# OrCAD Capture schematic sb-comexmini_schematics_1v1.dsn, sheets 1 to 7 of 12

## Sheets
1 INDEX: title: INDEX; rev: 1.0; note: 8001006002
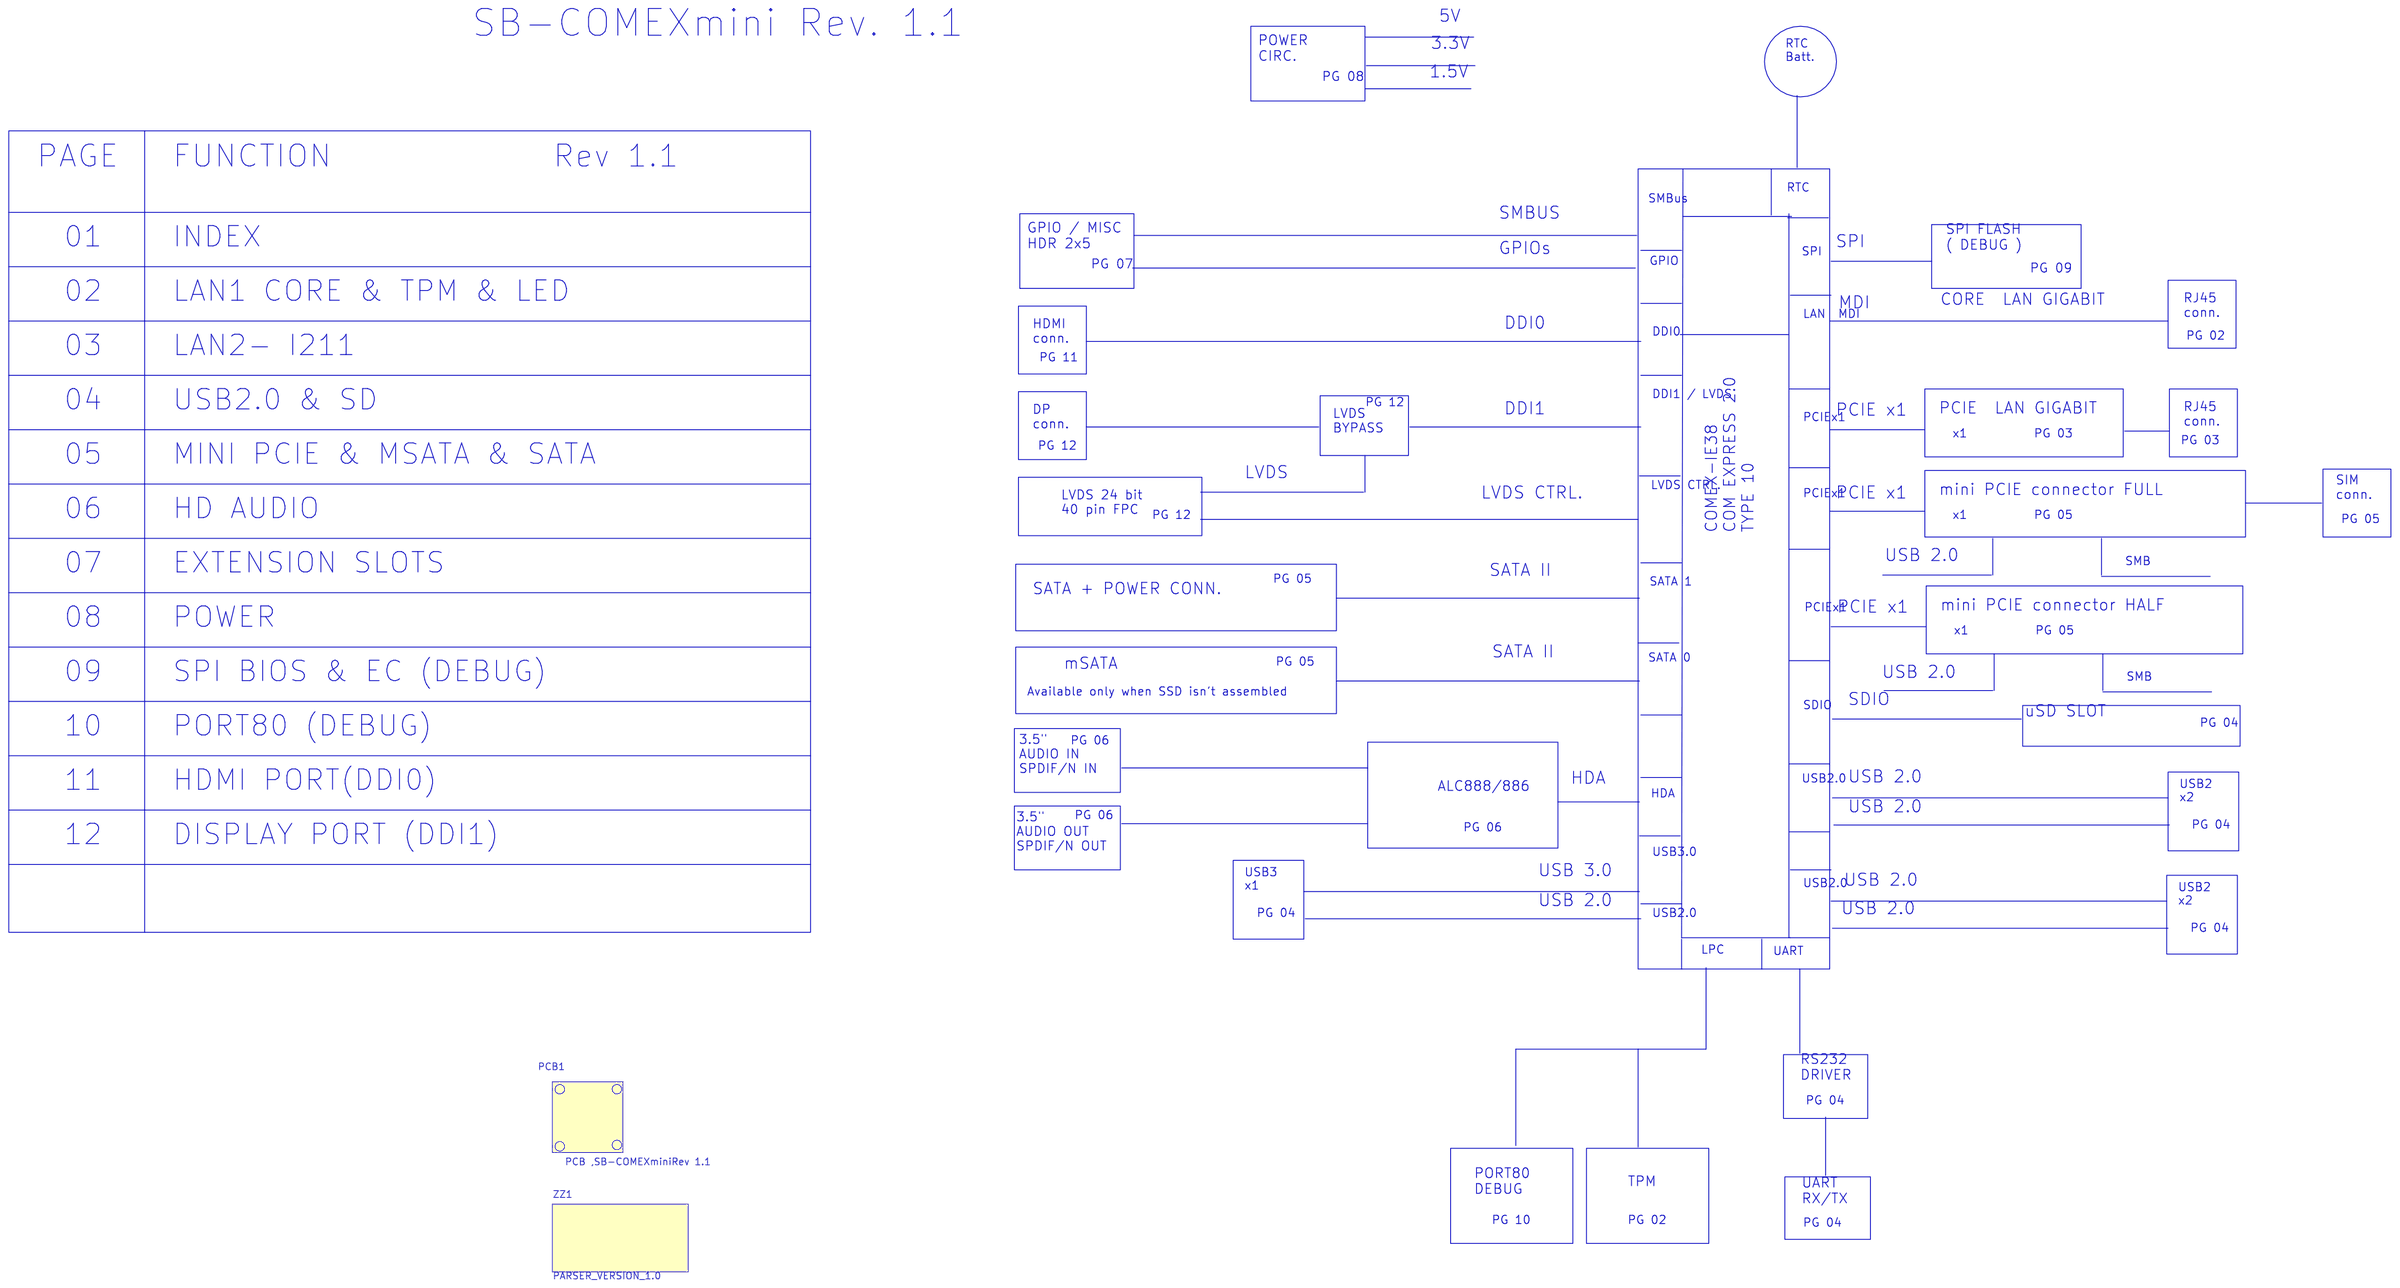
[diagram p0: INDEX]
2 LAN1 CORE & TPM & LED: size Custom; title: LAN1 CORE /TMP /LED
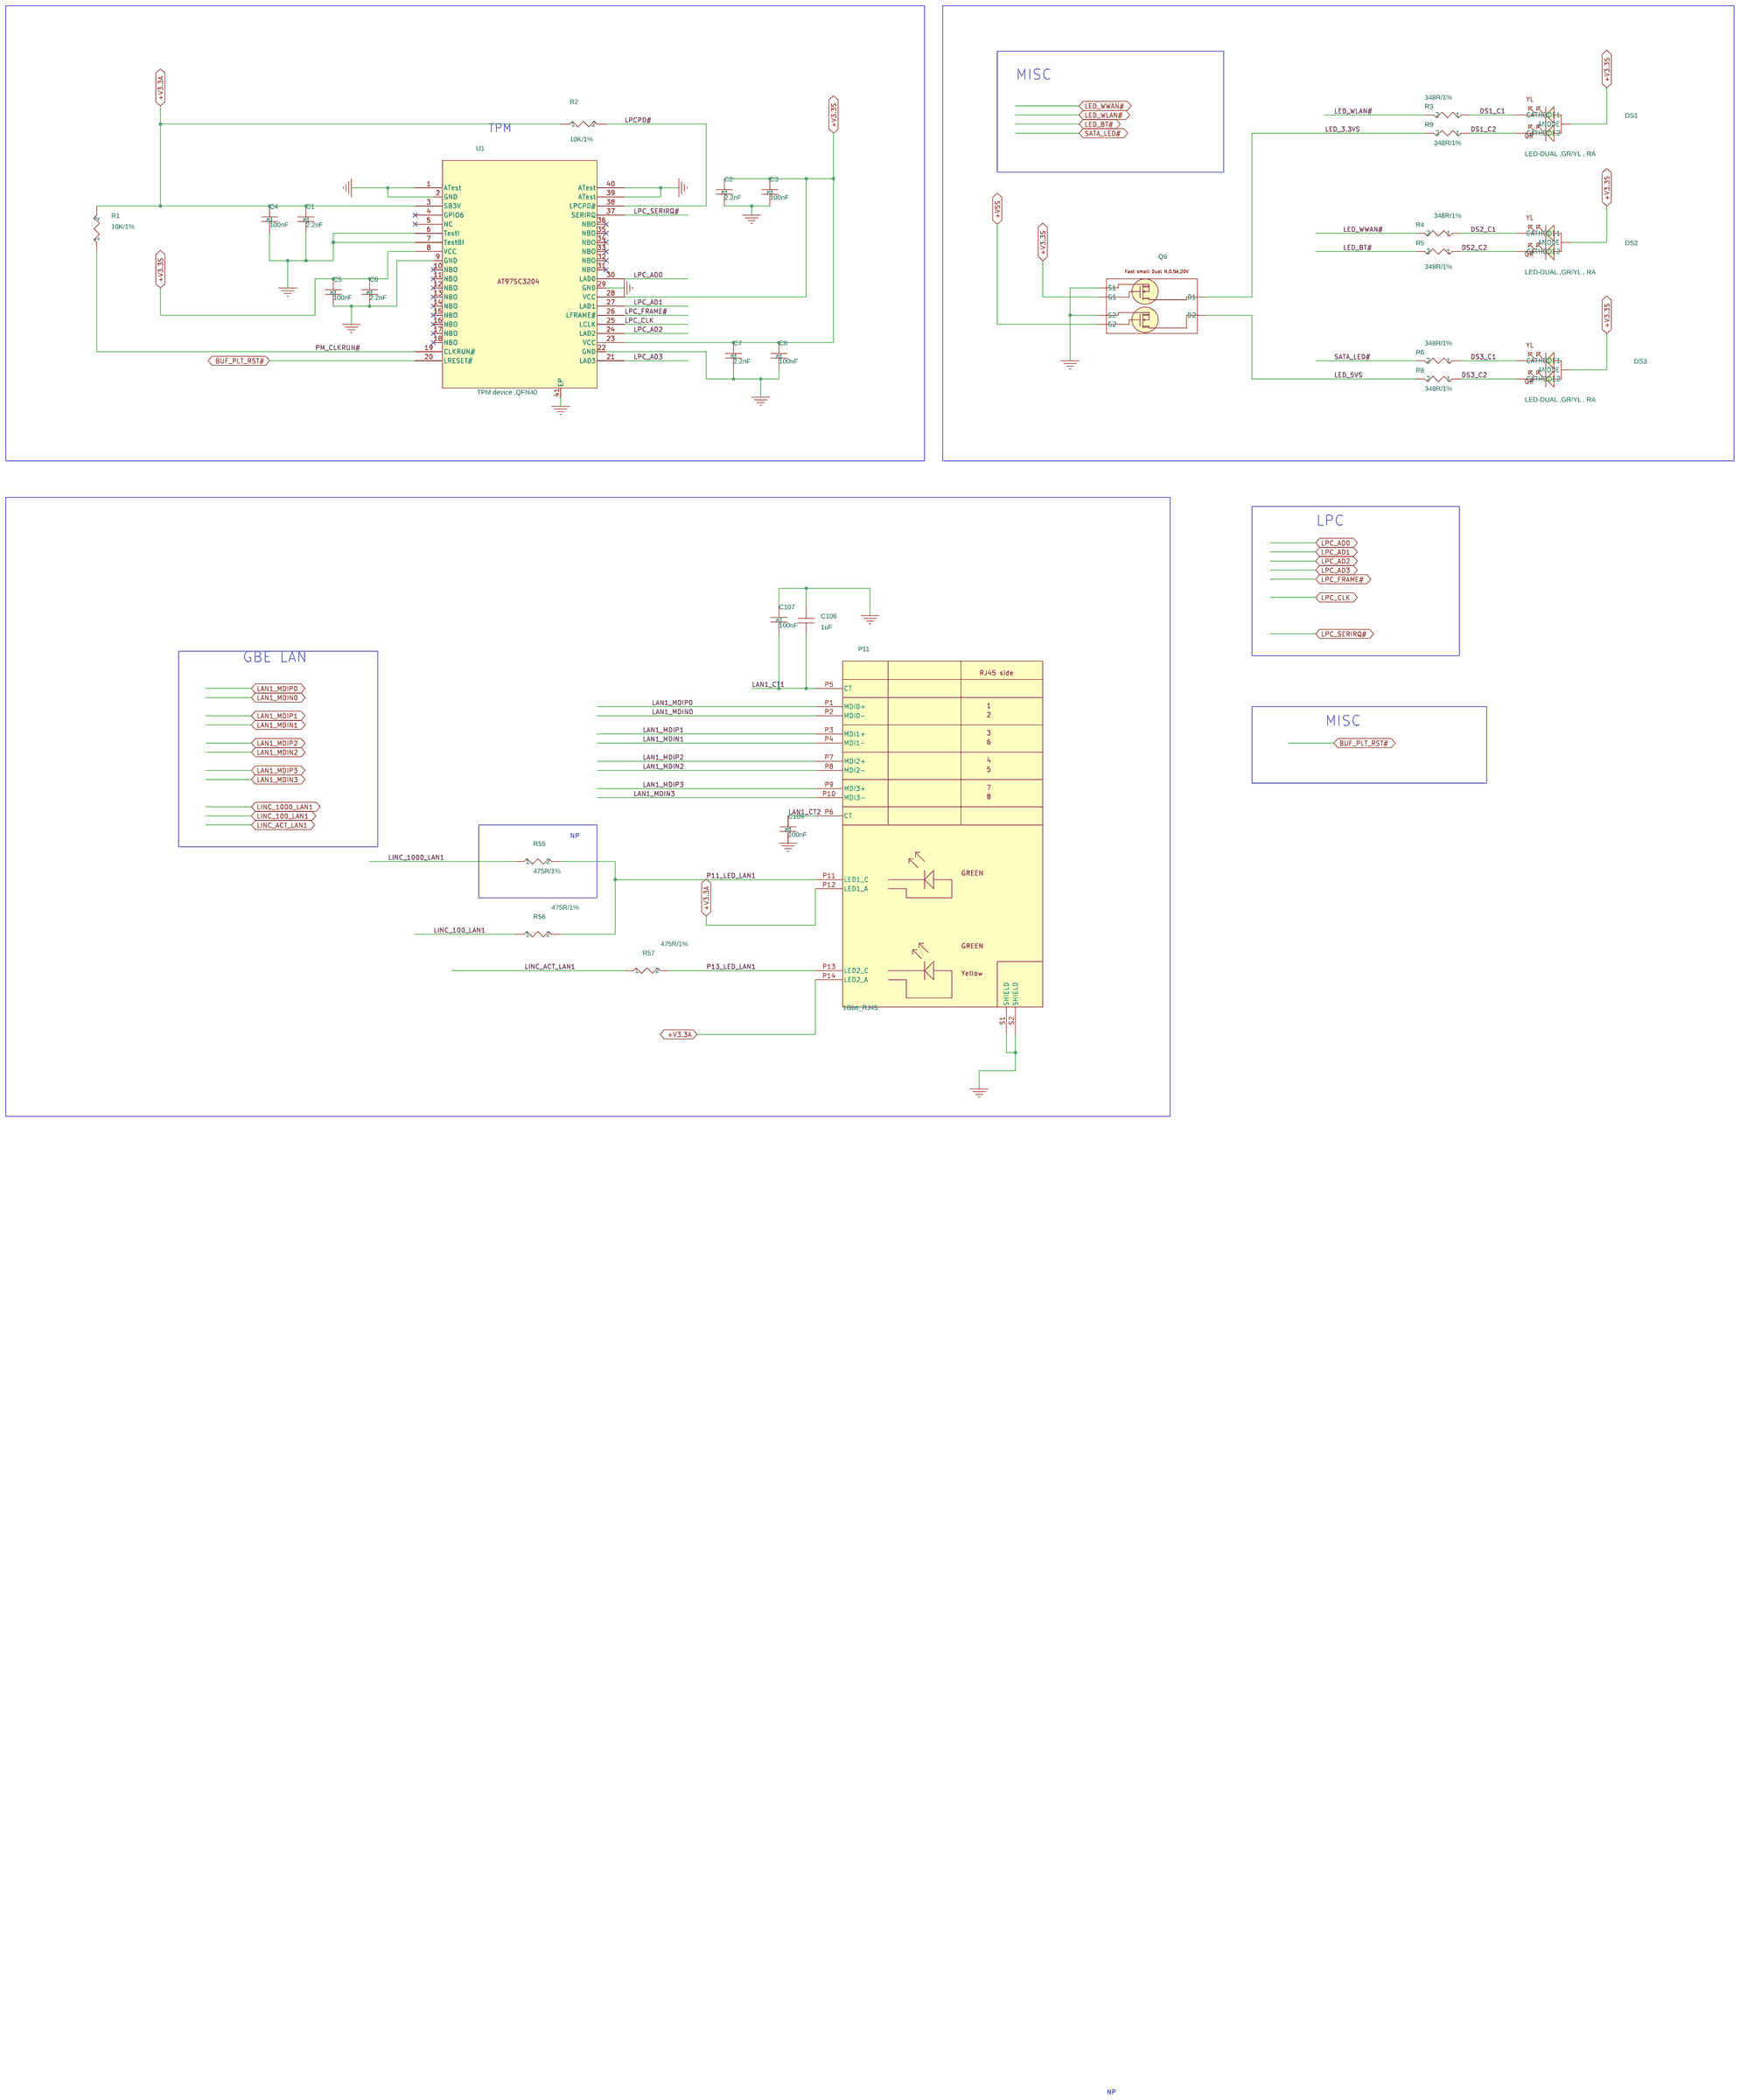
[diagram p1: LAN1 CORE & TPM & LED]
3 LAN2- I211: size Custom; title: LAN2 -I211
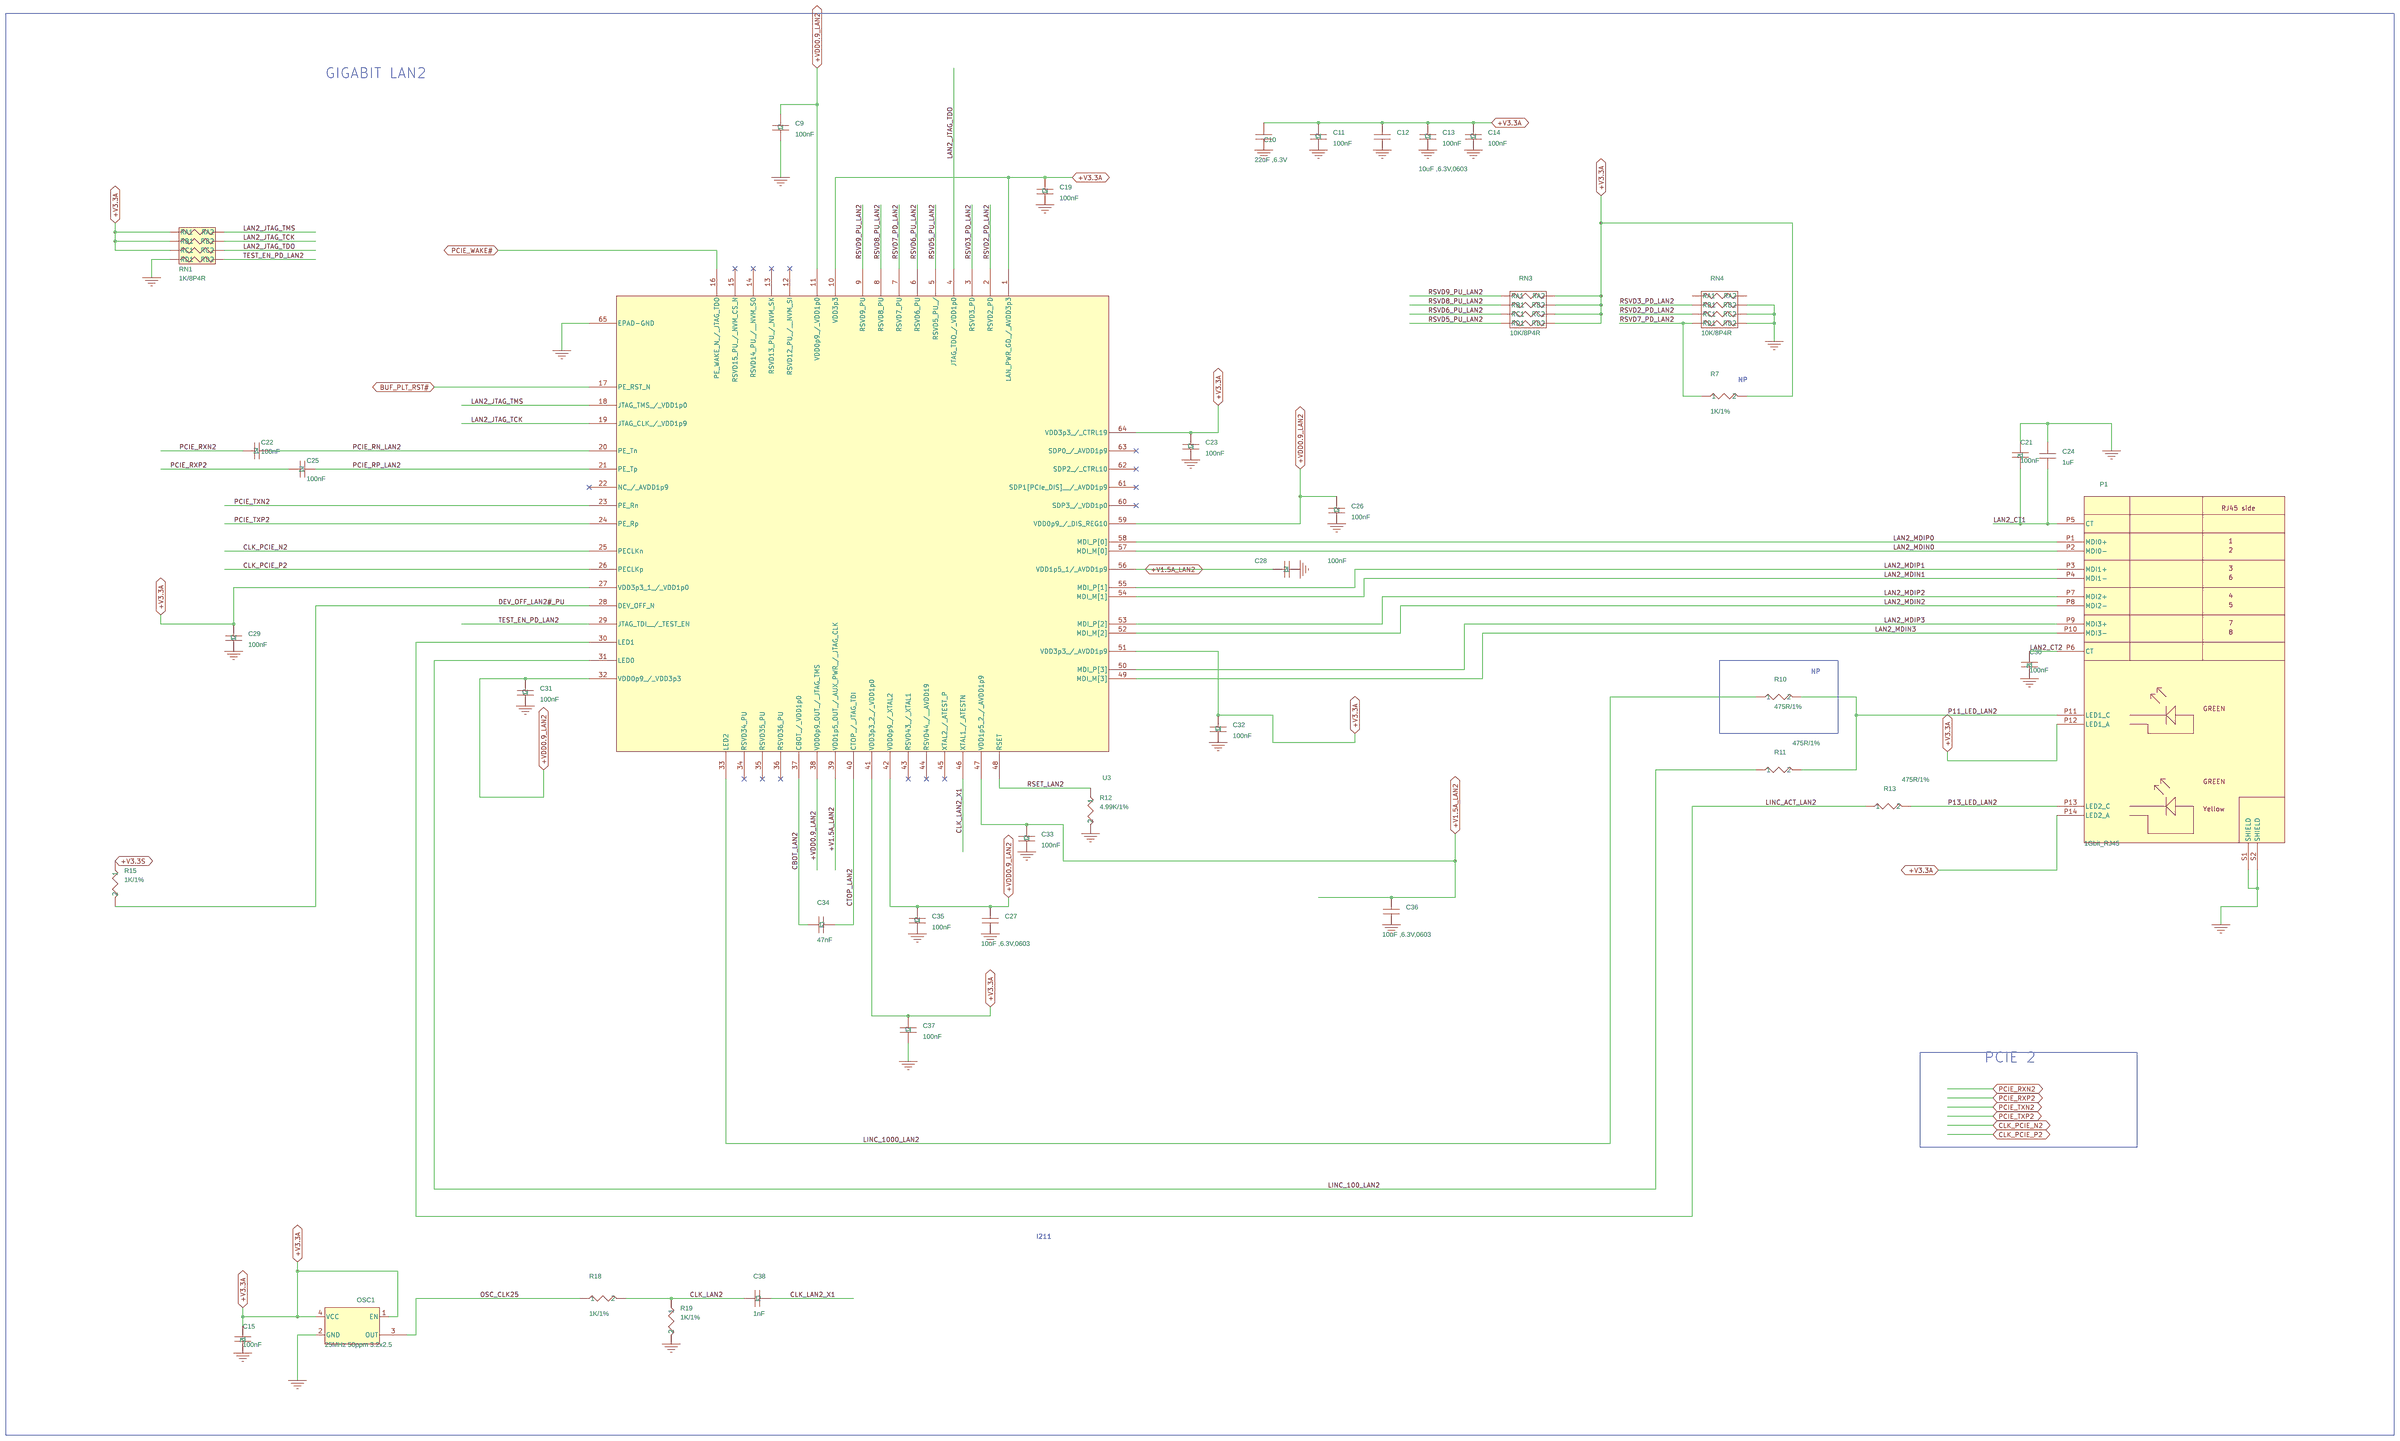
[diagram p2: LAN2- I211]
4 USB2.0 & SD: size Custom; title: USB3 / USB2 / SD
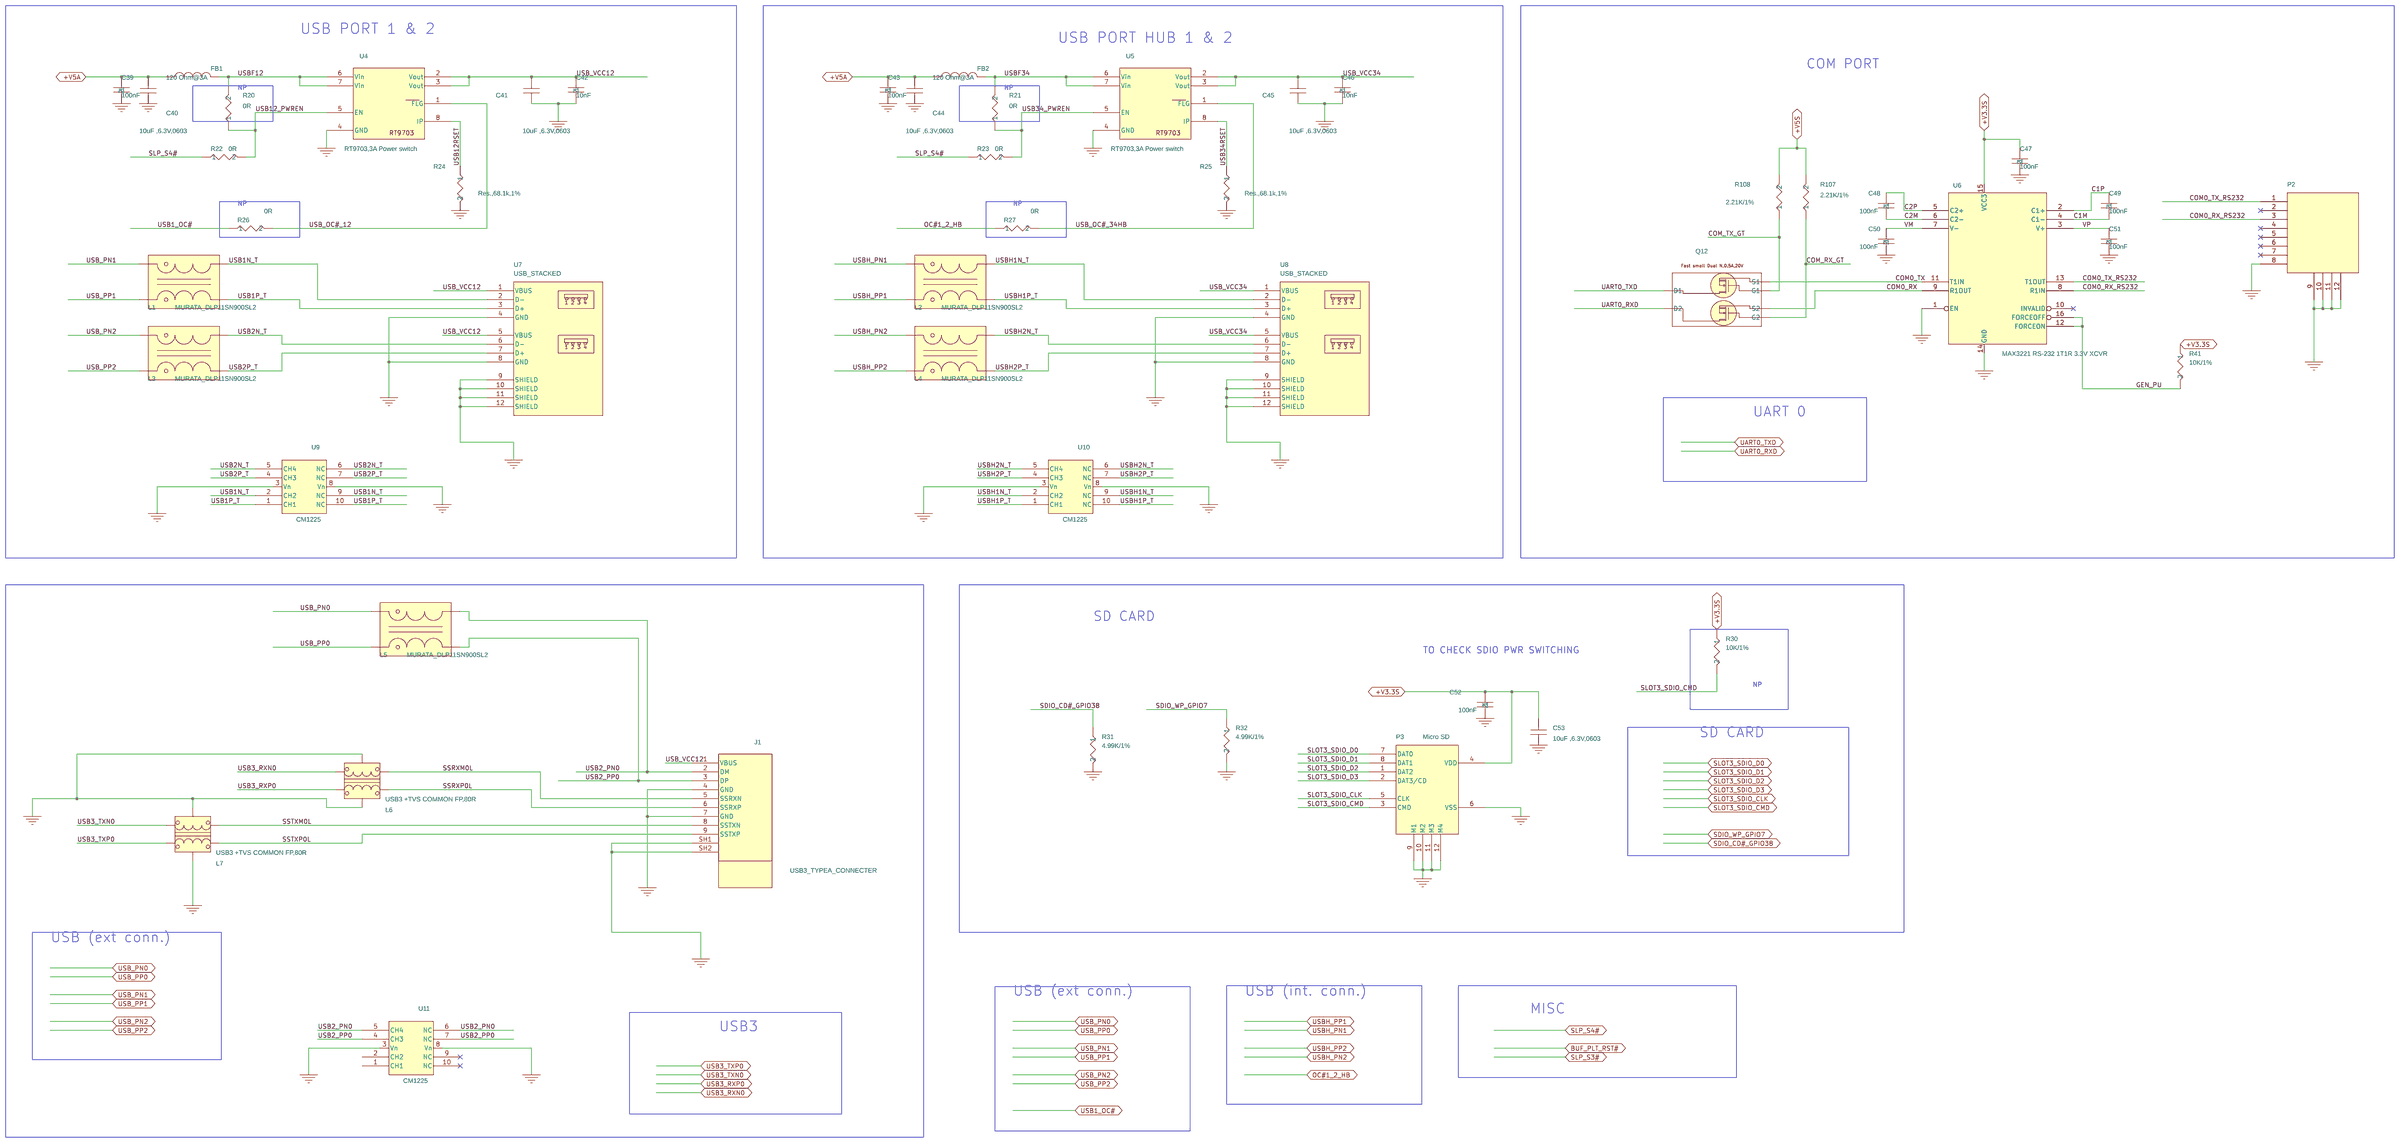
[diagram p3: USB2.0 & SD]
5 MINI PCIE & MSATA & SATA: size Custom; title: MINI PCIE & MSATA; note: 8005536002
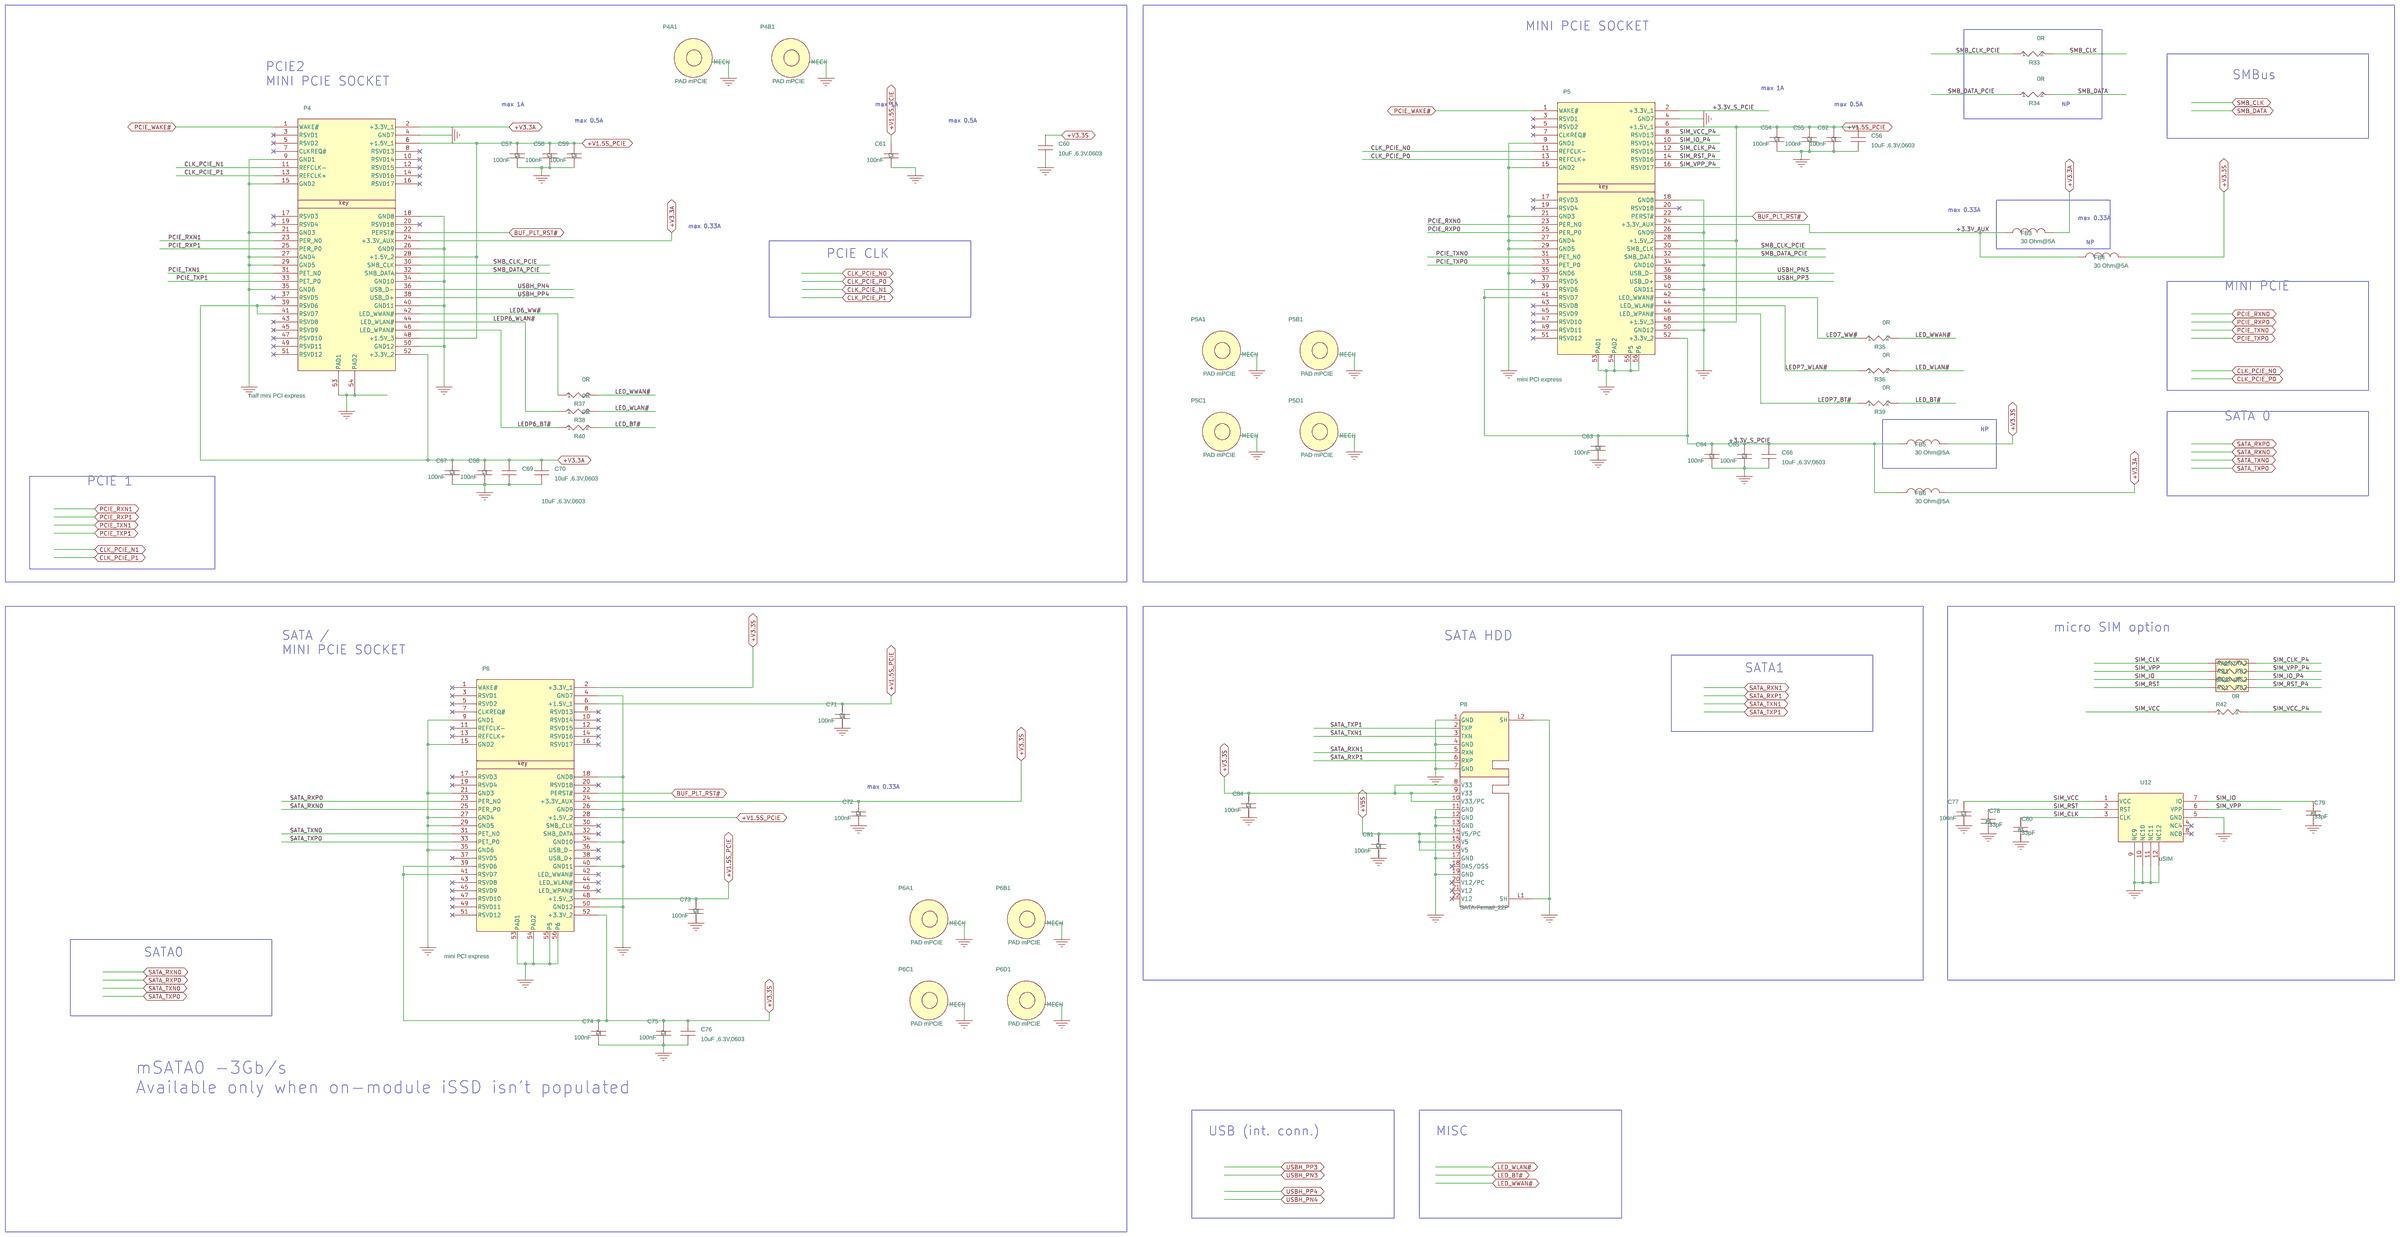
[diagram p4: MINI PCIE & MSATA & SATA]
6 HD AUDIO: size Custom; title: HD Audio
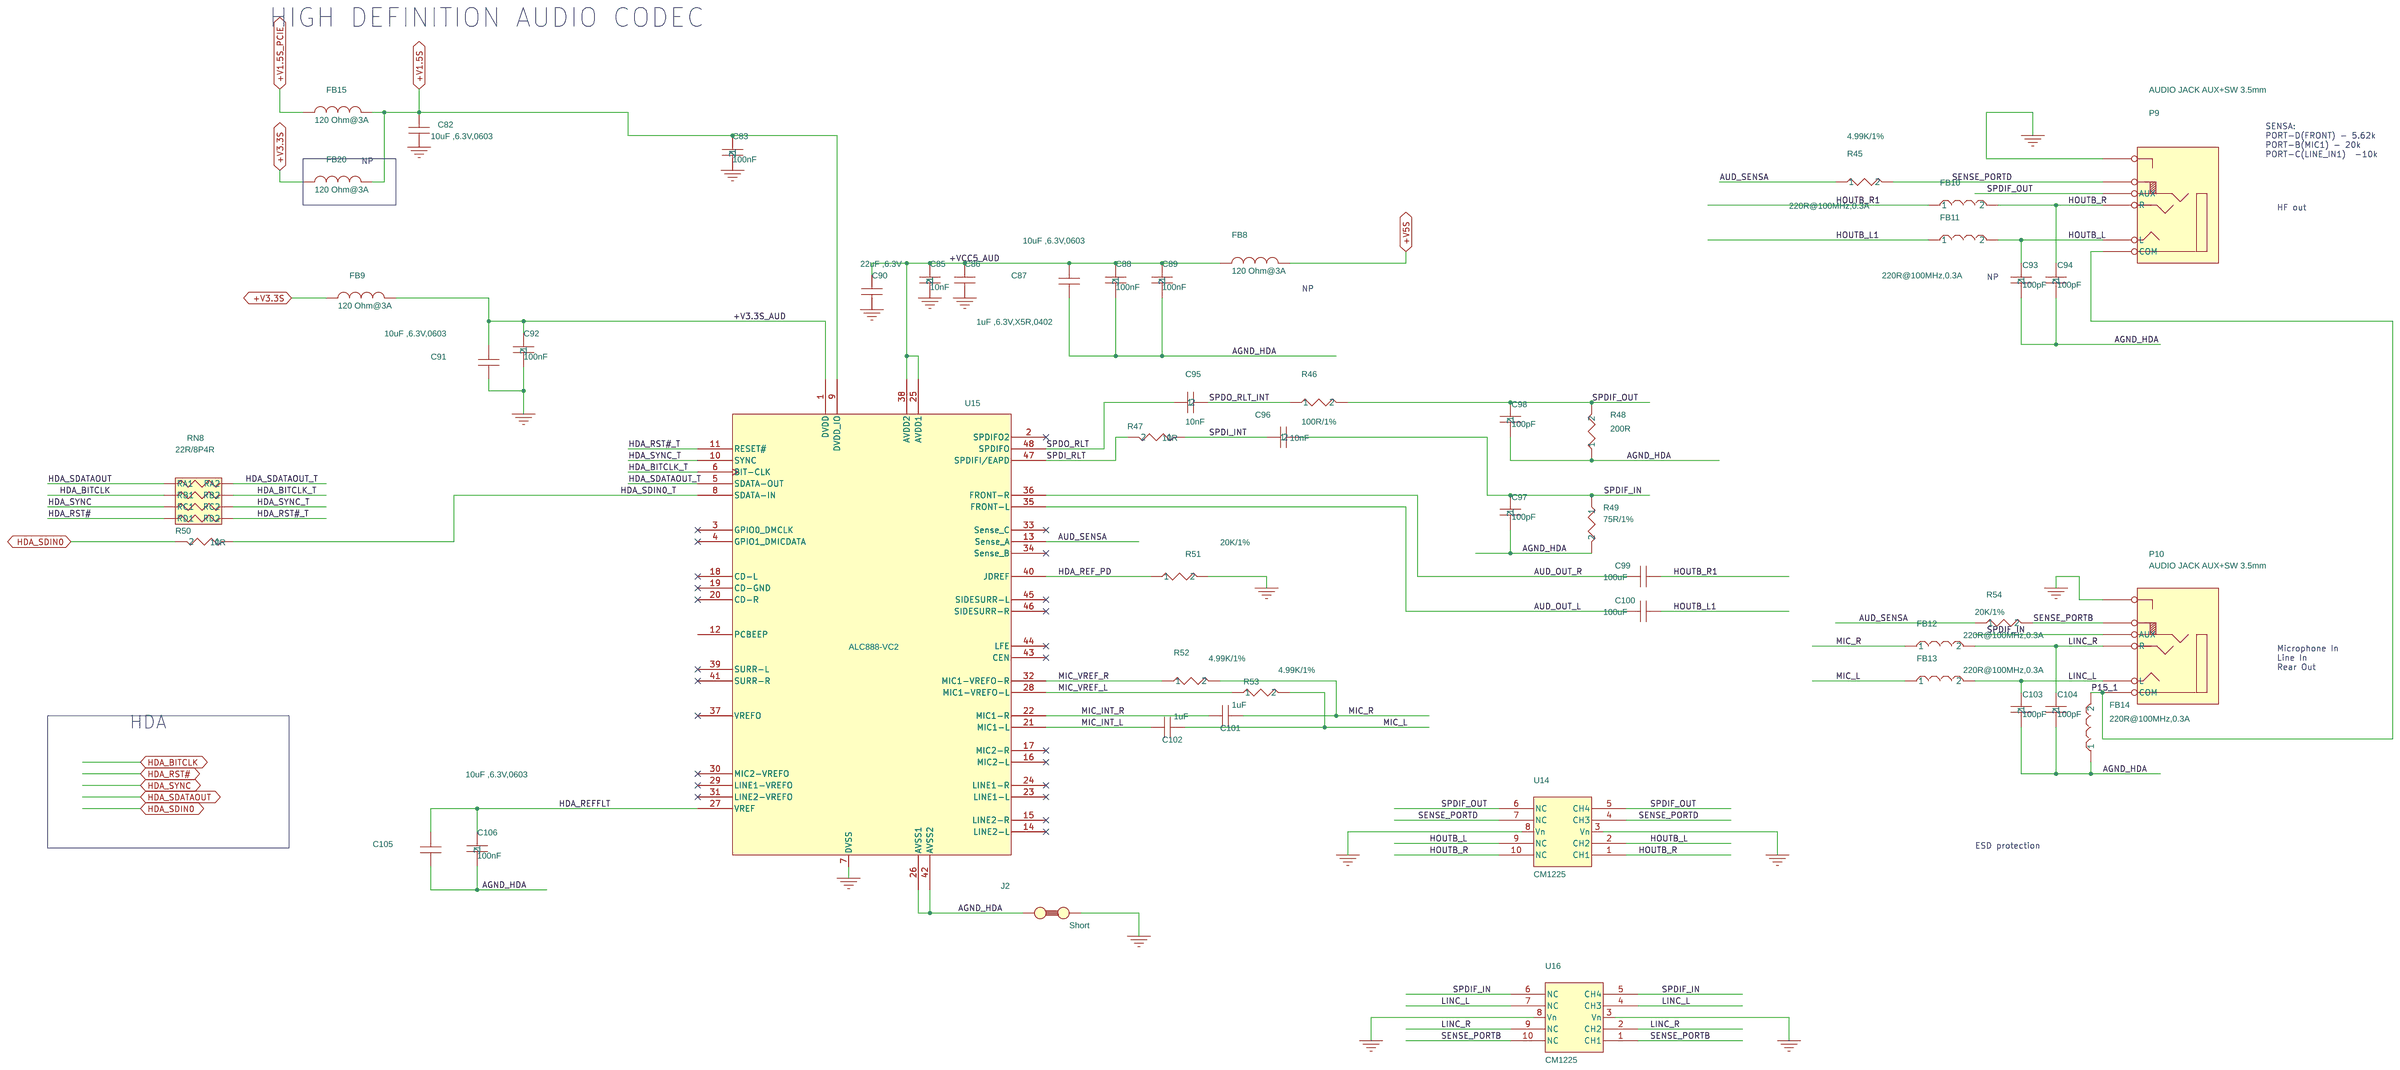
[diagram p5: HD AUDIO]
7 EXTENSION SLOTS: size Custom; title: EXTENSION CONN; note: 8005536002
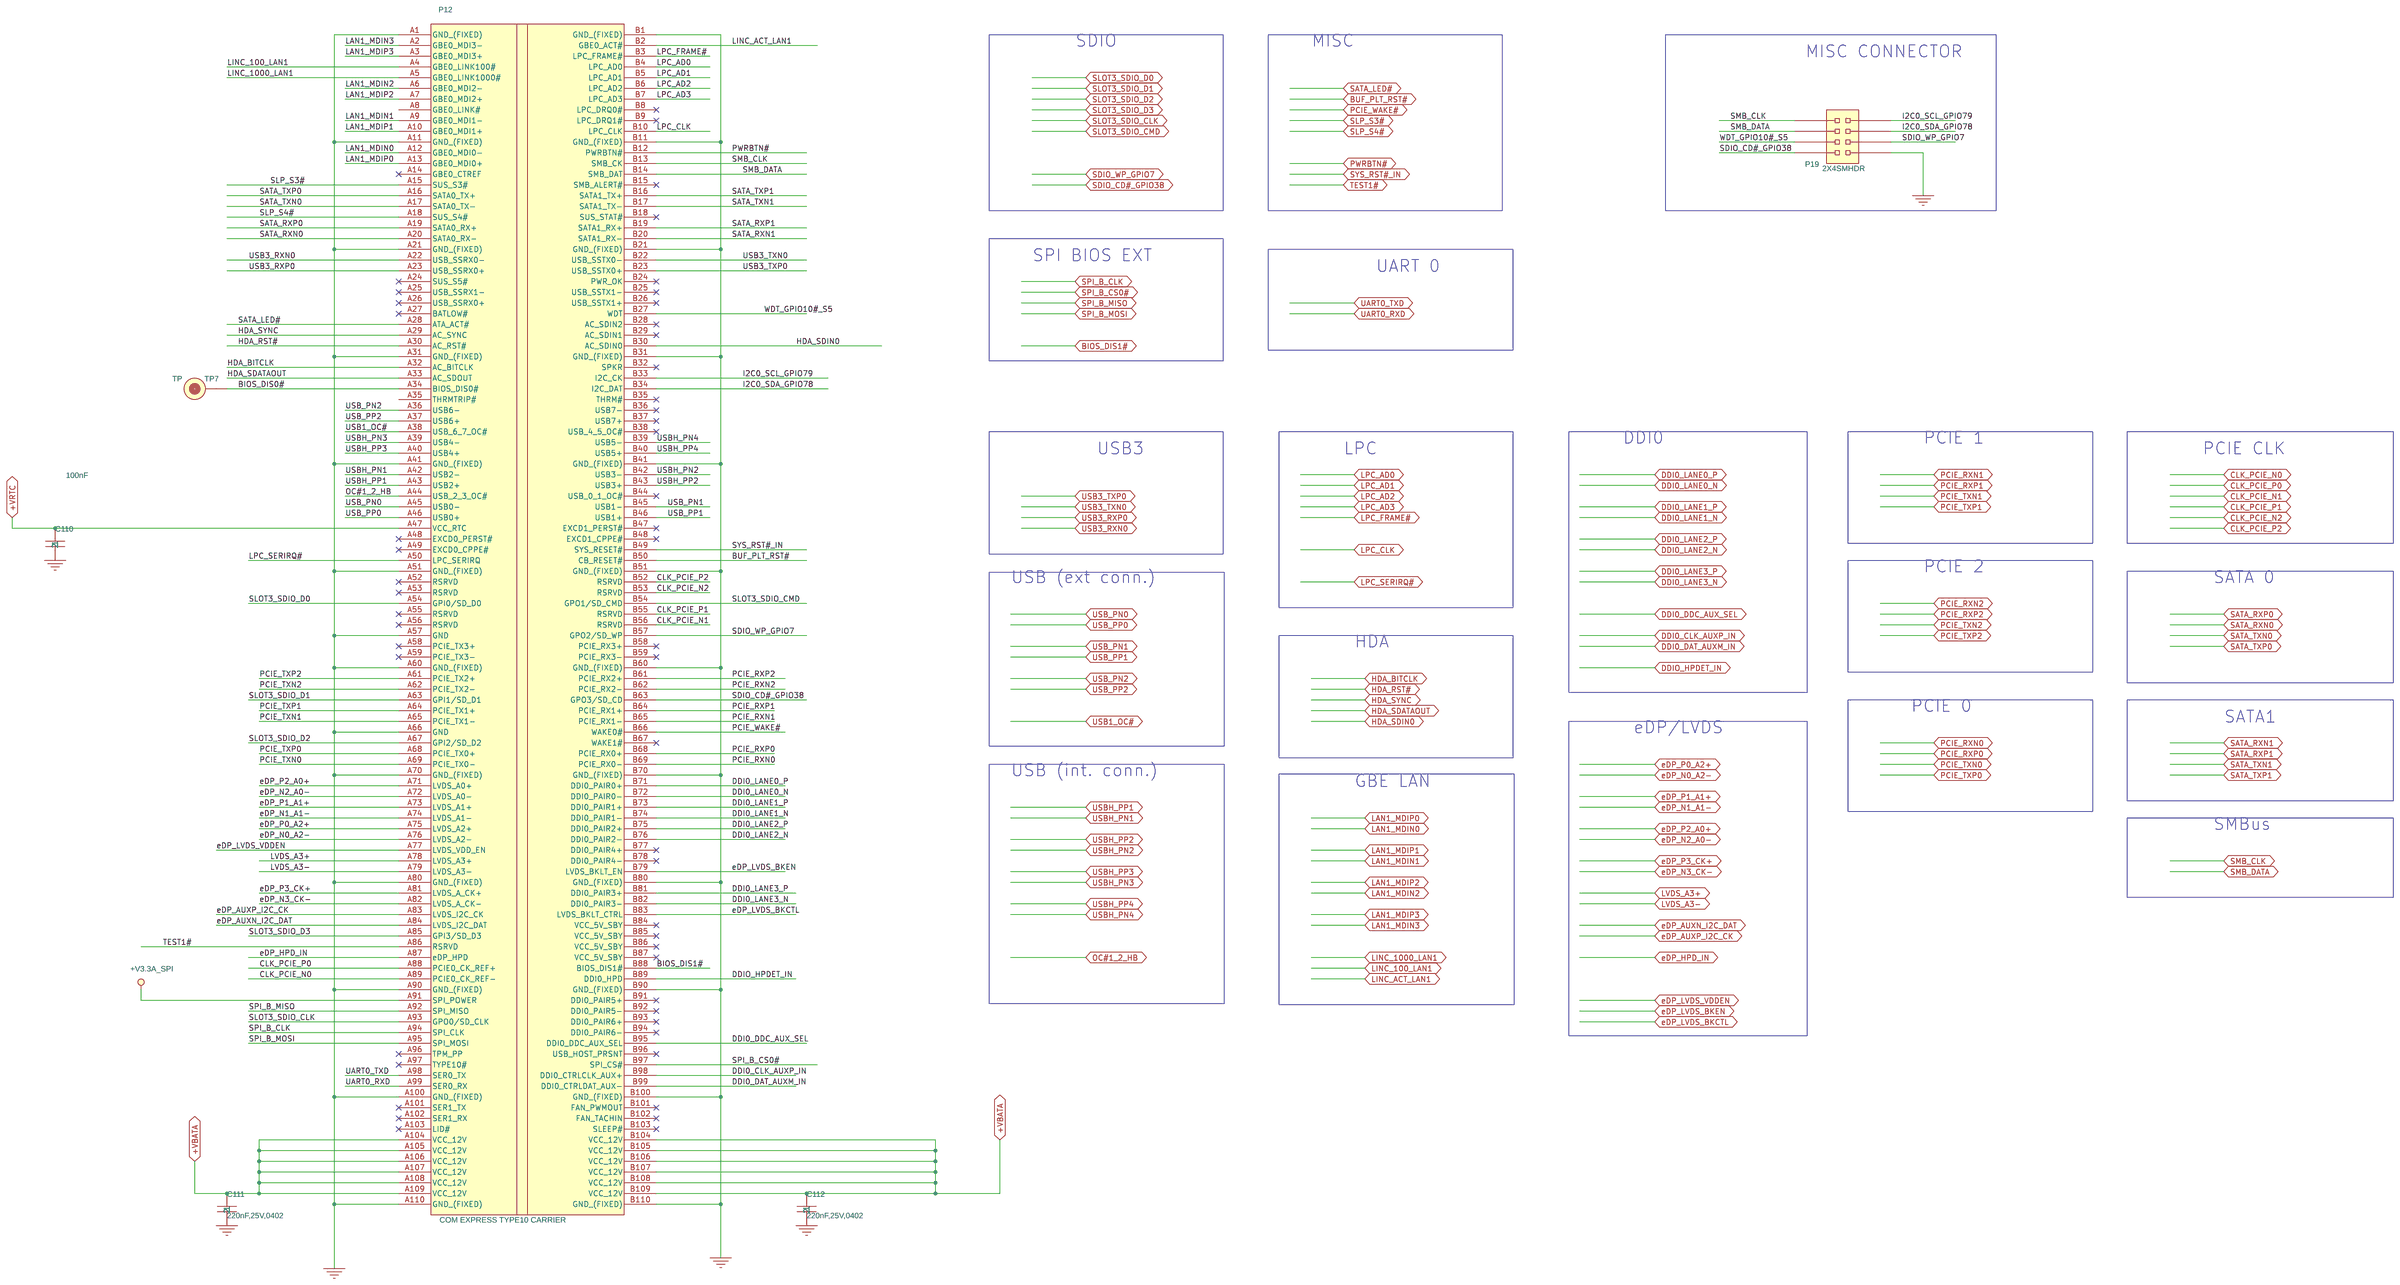
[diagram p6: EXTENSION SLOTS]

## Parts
sheet EXTENSION SLOTS
C110  100nF  [RC0402]
C111  220nF,25V,0402  [RC0402]
C112  220nF,25V,0402  [RC0402]
P12  COM EXPRESS TYPE10 CARRIER  [B2B05M2x110R]
P19  2X4SMHDR  [2X4SMHDR]
TP7  TP
sheet HD AUDIO
C82  10uF ,6.3V,0603  [RC0603]
C83  100nF  [RC0402]
C85  10nF  [RC0402]
C86  1uF ,6.3V,X5R,0402  [RC0402]
C87  10uF ,6.3V,0603  [RC0603]
C88  100nF  [RC0402]
C89  100nF  [RC0402]
C90  22uF ,6.3V  [0805]
C91  10uF ,6.3V,0603  [RC0603]
C92  100nF  [RC0402]
C93  100pF  [RC0402]
C94  100pF  [RC0402]
C95  10nF  [RC0402]
C96  10nF  [RC0402]
C97  100pF  [RC0402]
C98  100pF  [RC0402]
C99  100uF  [C1210H2_5]
C100  100uF  [C1210H2_5]
C101  1uF  [RC0402]
C102  1uF  [RC0402]
C103  100pF  [RC0402]
C104  100pF  [RC0402]
C105  10uF ,6.3V,0603  [RC0603]
C106  100nF  [RC0402]
FB8  120 Ohm@3A  [FB1206]
FB9  120 Ohm@3A  [FB1206]
FB10  220R@100MHz,0.3A  [FB0402]
FB11  220R@100MHz,0.3A  [FB0402]
FB12  220R@100MHz,0.3A  [FB0402]
FB13  220R@100MHz,0.3A  [FB0402]
FB14  220R@100MHz,0.3A  [FB0402]
FB15  120 Ohm@3A  [FB1206]
FB20  120 Ohm@3A  [FB1206]
J2  Short
P9  AUDIO JACK AUX+SW 3.5mm  [AJ35-4P-SW-SM]
P10  AUDIO JACK AUX+SW 3.5mm  [AJ35-4P-SW-SM]
R45  4.99K/1%  [RC0402]
R46  100R/1%  [RC0402]
R47  10R  [RC0402]
R48  200R  [RC0402]
R49  75R/1%  [RC0402]
R50  10R  [RC0402]
R51  20K/1%  [RC0402]
R52  4.99K/1%  [RC0402]
R53  4.99K/1%  [RC0402]
R54  20K/1%  [RC0402]
RN8  22R/8P4R  [RESNET8P0805]
U14  CM1225  [DFN-X2510D-10]
U15  ALC888-VC2  [LQFP48]
U16  CM1225  [DFN-X2510D-10]
sheet INDEX
PCB1  PCB ,SB-COMEXminiRev 1.1
ZZ1  PARSER_VERSION_1.0
sheet LAN1 CORE & TPM & LED
C1  2.2nF  [RC0402]
C2  2.2nF  [RC0402]
C3  100nF  [RC0402]
C4  100nF  [RC0402]
C5  100nF  [RC0402]
C6  2.2nF  [RC0402]
C7  2.2nF  [RC0402]
C8  100nF  [RC0402]
C107  100nF  [RC0402]
C108  1uF  [RC0402]
C109  100nF  [RC0402]
DS1  LED-DUAL ,GR/YL , RA  [LED3x1RASM]
DS2  LED-DUAL ,GR/YL , RA  [LED3x1RASM]
DS3  LED-DUAL ,GR/YL , RA  [LED3x1RASM]
P11  1Gbit_RJ45  [DUSBRJ-1G]
Q9  MOSFET,DUAL-N,0.4A@20V  [SOT-563-6]
R1  10K/1%  [RC0402]
R2  10K/1%  [RC0402]
R3  348R/1%  [RC0402]
R4  348R/1%  [RC0402]
R5  348R/1%  [RC0402]
R6  348R/1%  [RC0402]
R8  348R/1%  [RC0402]
R9  348R/1%  [RC0402]
R55  475R/1%  [RC0402]
R56  475R/1%  [RC0402]
R57  475R/1%  [RC0402]
U1  TPM device ,QFN40  [QFN-40]
sheet LAN2- I211
C9  100nF  [RC0402]
C10  22uF ,6.3V  [0805]
C11  100nF  [RC0402]
C12  10uF ,6.3V,0603  [RC0603]
C13  100nF  [RC0402]
C14  100nF  [RC0402]
C15  100nF  [RC0402]
C19  100nF  [RC0402]
C21  100nF  [RC0402]
C22  100nF  [RC0402]
C23  100nF  [RC0402]
C24  1uF  [RC0402]
C25  100nF  [RC0402]
C26  100nF  [RC0402]
C27  10uF ,6.3V,0603  [RC0603]
C28  100nF  [RC0402]
C29  100nF  [RC0402]
C30  100nF  [RC0402]
C31  100nF  [RC0402]
C32  100nF  [RC0402]
C33  100nF  [RC0402]
C34  47nF  [RC0603]
C35  100nF  [RC0402]
C36  10uF ,6.3V,0603  [RC0603]
C37  100nF  [RC0402]
C38  1nF  [RC0402]
OSC1  25MHz 50ppm 3.2x2.5  [OSC3225]
P1  1Gbit_RJ45  [DUSBRJ-1G]
R7  1K/1%  [RC0402]
R10  475R/1%  [RC0402]
R11  475R/1%  [RC0402]
R12  4.99K/1%  [RC0402]
R13  475R/1%  [RC0402]
R15  1K/1%  [RC0402]
R18  1K/1%  [RC0402]
R19  1K/1%  [RC0402]
RN1  1K/8P4R  [RESNET8P0805]
RN3  10K/8P4R  [RESNET8P0805]
RN4  10K/8P4R  [RESNET8P0805]
U3  I211 / 82583
sheet MINI PCIE & MSATA & SATA
C54  100nF  [RC0402]
C55  100nF  [RC0402]
C56  10uF ,6.3V,0603  [RC0603]
C57  100nF  [RC0402]
C58  100nF  [RC0402]
C59  100nF  [RC0402]
C60  10uF ,6.3V,0603  [RC0603]
C61  100nF  [RC0402]
C62  100nF  [RC0402]
C63  100nF  [RC0402]
C64  100nF  [RC0402]
C65  100nF  [RC0402]
C66  10uF ,6.3V,0603  [RC0603]
C67  100nF  [RC0402]
C68  100nF  [RC0402]
C69  10uF ,6.3V,0603  [RC0603]
C70  10uF ,6.3V,0603  [RC0603]
C71  100nF  [RC0402]
C72  100nF  [RC0402]
C73  100nF  [RC0402]
C74  100nF  [RC0402]
C75  100nF  [RC0402]
C76  10uF ,6.3V,0603  [RC0603]
C77  100nF  [RC0402]
C78  33pF  [RC0402]
C79  33pF  [RC0402]
C80  33pF  [RC0402]
C81  100nF  [RC0402]
C84  100nF  [RC0402]
FB3  30 Ohm@5A  [FB0603]
FB4  30 Ohm@5A  [FB0603]
FB5  30 Ohm@5A  [FB0603]
FB6  30 Ohm@5A  [FB0603]
P4  half mini PCI express  [MINIPCIE-4]
P4A1  PAD mPCIE  [TMP_PAD_PCIE]
P4B1  PAD mPCIE  [TMP_PAD_PCIE]
P5  mini PCI express  [MINIPCIE-4]
P5A1  PAD mPCIE  [TMP_PAD_PCIE]
P5B1  PAD mPCIE  [TMP_PAD_PCIE]
P5C1  PAD mPCIE  [TMP_PAD_PCIE]
P5D1  PAD mPCIE  [TMP_PAD_PCIE]
P6  mini PCI express  [MINIPCIE-4]
P6A1  PAD mPCIE  [TMP_PAD_PCIE]
P6B1  PAD mPCIE  [TMP_PAD_PCIE]
P6C1  PAD mPCIE  [TMP_PAD_PCIE]
P6D1  PAD mPCIE  [TMP_PAD_PCIE]
P8  SATA-Femail_22P  [SATA-22-V-TH]
R33  0R  [RC0402]
R34  0R  [RC0402]
R35  0R  [RC0402]
R36  0R  [RC0402]
R37  0R  [RC0402]
R38  0R  [RC0402]
R39  0R  [RC0402]
R40  0R  [RC0402]
R42  0R  [RC0402]
RN7  0R/8P4R  [RESNET8P0805]
U12  uSIM  [SKT-MicroSIM6-SM]
sheet USB2.0 & SD
C39  100nF  [RC0402]
C40  10uF ,6.3V,0603  [RC0603]
C41  10uF ,6.3V,0603  [RC0603]
C42  10nF  [RC0402]
C43  100nF  [RC0402]
C44  10uF ,6.3V,0603  [RC0603]
C45  10uF ,6.3V,0603  [RC0603]
C46  10nF  [RC0402]
C47  100nF  [RC0402]
C48  100nF  [RC0402]
C49  100nF  [RC0402]
C50  100nF  [RC0402]
C51  100nF  [RC0402]
C52  100nF  [RC0402]
C53  10uF ,6.3V,0603  [RC0603]
FB1  120 Ohm@3A  [FB1206]
FB2  120 Ohm@3A  [FB1206]
J1  USB3_TYPEA_CONNECTER  [USB3_TYPEA]
L1  MURATA_DLP11SN900SL2  [EMO1012]
L2  MURATA_DLP11SN900SL2  [EMO1012]
L3  MURATA_DLP11SN900SL2  [EMO1012]
L4  MURATA_DLP11SN900SL2  [EMO1012]
L5  MURATA_DLP11SN900SL2  [EMO1012]
L6  USB3 +TVS COMMON FP,80R  [EMI1012-ESD]
L7  USB3 +TVS COMMON FP,80R  [EMI1012-ESD]
P2  Ultra Mini Serial Connector  [UMS-8]
P3  Micro SD  [MicroSD-PP-RA-SM]
Q12  MOSFET,DUAL-N,0.4A@20V  [SOT-563-6]
R20  0R  [RC0402]
R21  0R  [RC0402]
R22  0R  [RC0402]
R23  0R  [RC0402]
R24  Res.,68.1k,1%  [0402]
R25  Res.,68.1k,1%  [0402]
R26  0R  [RC0402]
R27  0R  [RC0402]
R30  10K/1%  [RC0402]
R31  4.99K/1%  [RC0402]
R32  4.99K/1%  [RC0402]
R41  10K/1%  [RC0402]
R107  2.21K/1%
R108  2.21K/1%
U4  RT9703,3A Power switch  [SO-8-150]
U5  RT9703,3A Power switch  [SO-8-150]
U6  MAX3221 RS-232 1T1R 3.3V XCVR  [SSOP-16]
U7  USB_STACKED  [USB-2XA-TH]
U8  USB_STACKED  [USB-2XA-TH]
U9  CM1225  [DFN-X2510D-10]
U10  CM1225  [DFN-X2510D-10]
U11  CM1225  [DFN-X2510D-10]

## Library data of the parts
C110 = 100nF,_10V,_X7R,_10%,_0402: CLABCONF0: =SB-COMEXmini; Group: NPOP
C111 = 220nF,_25V,_X7R,_10%,_0402: CLABCONF0: =SB-COMEXmini
C112 = 220nF,_25V,_X7R,_10%,_0402_1: CLABCONF0: =SB-COMEXmini
P12 = COM-EXPRESS_TYP_10__CARR_CONN: CLABCONF0: =SB-COMEXmini
P19 = HDR_2x4_100MIL_SMT: CLABCONF0: =SB-COMEXmini
TP7 = TP_SMT
C82 = Cap.,10uF,6.3V,0603,X5R_3: CLABCONF1: =SB-COMEXmini
C83 = 100nF,_10V,_X7R,_10%,_0402: CLABCONF0: =A; CLABCONF1: =SB-COMEXmini; Group: AUD
C85 = 10nF,_25V,_X7R,_10%,_0402_1: CLABCONF0: =A; CLABCONF1: =SB-COMEXmini
C86 C101 C102 = Cap_1uF,X5R,6.3V,0402: CLABCONF0: =A; CLABCONF1: =SB-COMEXmini
C87 = Cap.,10uF,6.3V,0603,X5R_2: CLABCONF0: =A; CLABCONF1: =SB-COMEXmini
C88 = 100nF,_10V,_X7R,_10%,_0402_2: CLABCONF0: =A; CLABCONF1: =SB-COMEXmini; Group: AUD
C89 = 100nF,_10V,_X7R,_10%,_0402_4: CLABCONF0: =A; CLABCONF1: =SB-COMEXmini; Group: AUD
C90 = Cap.,22uF,6.3V,X5R: CLABCONF0: =A; CLABCONF1: =SB-COMEXmini
C91 = Cap.,10uF,6.3V,0603,X5R: CLABCONF0: =A; CLABCONF1: =SB-COMEXmini
C92 = 100nF,_10V,_X7R,_10%,_0402_3: CLABCONF0: =A; CLABCONF1: =SB-COMEXmini; Group: AUD
C93 = 100pF,_50V,_NPO,_5%,_0402_2: CLABCONF1: =SB-COMEXmini; Group: Always
C94 = 100pF,_50V,_NPO,_5%,_0402_4: CLABCONF1: =SB-COMEXmini; Group: Always
C95 = 10nF,_25V,_X7R,_10%,_0402: CLABCONF0: =A; CLABCONF1: =SB-COMEXmini
C96 = 10nF,_25V,_X7R,_10%,_0402_2: CLABCONF0: =A; CLABCONF1: =SB-COMEXmini
C97 = 100pF,_50V,_NPO,_5%,_0402_1: CLABCONF0: =A; CLABCONF1: =SB-COMEXmini; Group: Always
C98 = 100pF,_50V,_NPO,_5%,_0402: CLABCONF0: =A; CLABCONF1: =SB-COMEXmini; Group: Always
C99 C100 = 100uF,_6.3V,_X5R,_20%,_1206: CLABCONF0: =A; CLABCONF1: =SB-COMEXmini; Group: Always
C103 = 100pF,_50V,_NPO,_5%,_0402_3: CLABCONF1: =SB-COMEXmini; Group: Always
C104 = 100pF,_50V,_NPO,_5%,_0402_5: CLABCONF1: =SB-COMEXmini; Group: Always
C105 = Cap.,10uF,6.3V,0603,X5R_1: CLABCONF0: =A; CLABCONF1: =SB-COMEXmini
C106 = 100nF,_10V,_X7R,_10%,_0402_1: CLABCONF0: =A; CLABCONF1: =SB-COMEXmini; Group: NPOP
FB8 = Ferrite_bead_,_120_Ohm@3A_3: CLABCONF0: =A; CLABCONF1: =SB-COMEXmini
FB9 = Ferrite_bead_,_120_Ohm@3A_2: CLABCONF0: =A; CLABCONF1: =SB-COMEXmini
FB10 = Ferrit_220R@100Mhz,0.3A_1: CLABCONF1: =SB-COMEXmini
FB11 = Ferrit_220R@100Mhz,0.3A_4: CLABCONF1: =SB-COMEXmini
FB12 = Ferrit_220R@100Mhz,0.3A_3: CLABCONF1: =SB-COMEXmini
FB13 = Ferrit_220R@100Mhz,0.3A: CLABCONF1: =SB-COMEXmini
FB14 = Ferrit_220R@100Mhz,0.3A_2: CLABCONF1: =SB-COMEXmini
FB15 = Ferrite_bead_,_120_Ohm@3A_1: CLABCONF0: =A; CLABCONF1: =SB-COMEXmini
FB20 = Ferrite_bead_,_120_Ohm@3A: CLABCONF0: =NOP
J2 = Jumper0201
P9 P10 = Audio_JACK,_STEREO+AUX+SW_3.5mm: CLABCONF0: =A; CLABCONF1: =SB-COMEXmini
R45 = 4.99K,1%,0402,1_16W_1: CLABCONF1: =SB-COMEXmini
R46 = 100R,1%,0402,1_16W: CLABCONF0: =A; CLABCONF1: =SB-COMEXmini
R47 = 10R,_0402: CLABCONF0: =A; CLABCONF1: =SB-COMEXmini
R48 = 0R,_0402: CLABCONF0: =A; CLABCONF1: =SB-COMEXmini; P/N: 161C20001S
R49 = 75R,1%,0402,1_16W: CLABCONF0: =A; CLABCONF1: =SB-COMEXmini
R50 = 10R,_0402_1: CLABCONF0: =A; CLABCONF1: =SB-COMEXmini
R51 = 20K_1%,_0402_1: CLABCONF1: =SB-COMEXmini; Group: AUD
R52 = 4.99K,1%,0402,1_16W_2: CLABCONF0: =A; CLABCONF1: =SB-COMEXmini
R53 = 4.99K,1%,0402,1_16W: CLABCONF0: =A; CLABCONF1: =SB-COMEXmini
R54 = 20K_1%,_0402: CLABCONF1: =SB-COMEXmini
RN8 = RN,22R,8P4R@0805_0: CLABCONF0: =A; CLABCONF1: =SB-COMEXmini
U14 U16 = IC,ESD_Diode,0.25pF_,x4: CLABCONF1: =SB-COMEXmini
U15 = ALC888-LQFP48_2: CLABCONF0: 117A08880S=A; CLABCONF1: 117A08880S=SB-COMEXmini
PCB1 = PCB_SB-COMEXT10: CLABCONF0: 188C02841=SB-COMEXmini
ZZ1 = PARSER_VERSION_1.0
C1 = 2.2nF,_50V,_X7R,_10%,_0402_3: CLABCONF0: =SB-COMEXmini
C2 = 2.2nF,_50V,_X7R,_10%,_0402_1: CLABCONF0: =SB-COMEXmini
C3 = 100nF,_10V,_X7R,_10%,_0402_2: CLABCONF0: =SB-COMEXmini; Group: ALL
C4 = 100nF,_10V,_X7R,_10%,_0402: CLABCONF0: =SB-COMEXmini; Group: ALL
C5 = 100nF,_10V,_X7R,_10%,_0402_5: CLABCONF0: =SB-COMEXmini; Group: ALL
C6 = 2.2nF,_50V,_X7R,_10%,_0402: CLABCONF0: =SB-COMEXmini
C7 = 2.2nF,_50V,_X7R,_10%,_0402_2: CLABCONF0: =SB-COMEXmini
C8 = 100nF,_10V,_X7R,_10%,_0402_3: CLABCONF0: =SB-COMEXmini; Group: ALL
C107 = 100nF,_10V,_X7R,_10%,_0402_4: CLABCONF0: =E1; CLABCONF1: =SB-COMEXmini; Group: LAN2
C108 = Cap_1uF,X5R,6.3V,0402: CLABCONF0: =E1; CLABCONF1: =SB-COMEXmini
C109 = 100nF,_10V,_X7R,_10%,_0402_1: CLABCONF0: =E1; CLABCONF1: =SB-COMEXmini; Group: LAN2
DS1-DS3 = LED,_Dual,ip_3x1mm,_R_A,_G_Y_0: CLABCONF0: =SB-COMEXmini
P11 = Con.,1GBit_RJ45,_short: CLABCONF0: =E1; CLABCONF1: =SB-COMEXmini
Q9 Q12 = MOSFET,DUAL-N,0.4A@20V: CLABCONF0: =SB-COMEXmini
R1 = 10K,1%,0402,1_16W_1: CLABCONF0: =SB-COMEXmini
R2 R41 = 10K,1%,0402,1_16W: CLABCONF0: =SB-COMEXmini
R3 = 348R,1%,0402,1_16W_2: CLABCONF0: =SB-COMEXmini
R4 = 348R,1%,0402,1_16W_3: CLABCONF0: =SB-COMEXmini
R5 = 348R,1%,0402,1_16W_5: CLABCONF0: =SB-COMEXmini
R6 = 348R,1%,0402,1_16W_1: CLABCONF0: =SB-COMEXmini
R8 = 348R,1%,0402,1_16W_4: CLABCONF0: =SB-COMEXmini
R9 = 348R,1%,0402,1_16W: CLABCONF0: =SB-COMEXmini
R55 = 475R_1%,_0402_1: CLABCONF0: =NOP
R56 = 475R_1%,_0402_2: CLABCONF0: =E1; CLABCONF1: =SB-COMEXmini
R57 = 475R_1%,_0402: CLABCONF0: =E1; CLABCONF1: =SB-COMEXmini
U1 = IC.,TPM_V1.2_AT97SC3204: CLABCONF0: =SB-COMEXmini
C9 = 100nF,_10V,_X7R,_10%,_0402_6: CLABCONF0: =SB-COMEXmini; CLABCONF1: =E2
C10 = Cap.,22uF,6.3V,X5R: CLABCONF0: =SB-COMEXmini
C11 C73 = 100nF,_10V,_X7R,_10%,_0402_10: CLABCONF0: =SB-COMEXmini
C12 C45 C69 = Cap.,10uF,6.3V,0603,X5R: CLABCONF0: =SB-COMEXmini
C13 C84 = 100nF,_10V,_X7R,_10%,_0402_4: CLABCONF0: =SB-COMEXmini
C14 C61 = 100nF,_10V,_X7R,_10%,_0402_8: CLABCONF0: =SB-COMEXmini
C15 = 100nF,_10V,_X7R,_10%,_0402_15: CLABCONF0: =SB-COMEXmini; Group: LAN2
C19 = 100nF,_10V,_X7R,_10%,_0402_7: CLABCONF0: =SB-COMEXmini; CLABCONF1: =E2
C21 = 100nF,_10V,_X7R,_10%,_0402_14: CLABCONF0: =SB-COMEXmini; CLABCONF1: =E2; Group: LAN2
C22 = 100nF,_10V,_X7R,_10%,_0402_5: CLABCONF0: =SB-COMEXmini; CLABCONF1: =E2; Group: LAN2
C23 C67 = 100nF,_10V,_X7R,_10%,_0402_18: CLABCONF0: =SB-COMEXmini
C24 = Cap_1uF,X5R,6.3V,0402: CLABCONF0: =SB-COMEXmini; CLABCONF1: =E2
C25 = 100nF,_10V,_X7R,_10%,_0402: CLABCONF0: =SB-COMEXmini; CLABCONF1: =E2; Group: LAN2
C26 = 100nF,_10V,_X7R,_10%,_0402_3: CLABCONF0: =SB-COMEXmini; CLABCONF1: =E2
C27 = Cap.,10uF,6.3V,0603,X5R_2: CLABCONF0: =SB-COMEXmini; CLABCONF1: =E2
C28 = 100nF,_10V,_X7R,_10%,_0402_16: CLABCONF0: =SB-COMEXmini; CLABCONF1: =E2
C29 C58 = 100nF,_10V,_X7R,_10%,_0402_11: CLABCONF0: =SB-COMEXmini
C30 = 100nF,_10V,_X7R,_10%,_0402_17: CLABCONF0: =SB-COMEXmini; CLABCONF1: =E2; Group: LAN2
C31 C65 = 100nF,_10V,_X7R,_10%,_0402_9: CLABCONF0: =SB-COMEXmini
C32 C68 = 100nF,_10V,_X7R,_10%,_0402_1: CLABCONF0: =SB-COMEXmini
C33 = 100nF,_10V,_X7R,_10%,_0402_2: CLABCONF0: =SB-COMEXmini; CLABCONF1: =E2
C34 = 47nF,_25V,_X7R,_10%,_0603: CLABCONF0: =SB-COMEXmini; CLABCONF1: =E2
C35 = 100nF,_10V,_X7R,_10%,_0402_12: CLABCONF0: =SB-COMEXmini; CLABCONF1: =E2
C36 C41 C66 = Cap.,10uF,6.3V,0603,X5R_1: CLABCONF0: =SB-COMEXmini
C37 C57 = 100nF,_10V,_X7R,_10%,_0402_13: CLABCONF0: =SB-COMEXmini
C38 = 1nF,10%,_50V,_X7R,_0402: CLABCONF0: =SB-COMEXmini; CLABCONF1: =E2
OSC1 = 25MHz,50PPM,OSC3225,_3.3V: CLABCONF0: =SB-COMEXmini; CLABCONF1: =E2
P1 = Con.,1GBit_RJ45,_short: CLABCONF0: =SB-COMEXmini; CLABCONF1: =E2
R7 = 1K,1%,0402,1_16W_1: CLABCONF0: =NOP
R10 = 475R_1%,_0402: CLABCONF0: =NOP
R11 = 475R_1%,_0402_1: CLABCONF0: =SB-COMEXmini
R12 = 4.99K,1%,0402,1_16W: CLABCONF0: =SB-COMEXmini; CLABCONF1: =E2
R13 = 475R_1%,_0402_2: CLABCONF0: =SB-COMEXmini
R15 = 1K,1%,0402,1_16W: CLABCONF0: =SB-COMEXmini
R18 = 1K,1%,0402,1_16W_3: CLABCONF0: =SB-COMEXmini; CLABCONF1: =E2
R19 = 1K,1%,0402,1_16W_2: CLABCONF0: =SB-COMEXmini; CLABCONF1: =E2
RN1 = RN,1K,8P4R@0805: CLABCONF0: =SB-COMEXmini
RN3 RN4 = RN,10K,8P4R@0805: CLABCONF0: =SB-COMEXmini; CLABCONF1: =E2
U3 = IC,_I211_,PCIE_1Gb_LAN_0: CLABCONF0: 116B00070S=SB-COMEXmini; CLABCONF1: =E2; P/N: 116B00070S
C54 = 100nF,_10V,_X7R,_10%,_0402_12: CLABCONF0: =SB-COMEXmini
C55 = 100nF,_10V,_X7R,_10%,_0402_7: CLABCONF0: =SB-COMEXmini
C56 = Cap.,10uF,6.3V,0603,X5R_5: CLABCONF0: =SB-COMEXmini
C59 = 100nF,_10V,_X7R,_10%,_0402_17: CLABCONF0: =SB-COMEXmini
C44 C60 = Cap.,10uF,6.3V,0603,X5R_3: CLABCONF0: =SB-COMEXmini
C62 = 100nF,_10V,_X7R,_10%,_0402_14: CLABCONF0: =SB-COMEXmini
C63 = 100nF,_10V,_X7R,_10%,_0402_5: CLABCONF0: =SB-COMEXmini
C64 = 100nF,_10V,_X7R,_10%,_0402_6: CLABCONF0: =SB-COMEXmini
C40 C70 = Cap.,10uF,6.3V,0603,X5R_4: CLABCONF0: =SB-COMEXmini
C71 = 100nF,_10V,_X7R,_10%,_0402_15: CLABCONF0: =SB-COMEXmini
C72 = 100nF,_10V,_X7R,_10%,_0402_19: CLABCONF0: =SB-COMEXmini
C74 = 100nF,_10V,_X7R,_10%,_0402: CLABCONF0: =SB-COMEXmini
C75 = 100nF,_10V,_X7R,_10%,_0402_2: CLABCONF0: =SB-COMEXmini
C53 C76 = Cap.,10uF,6.3V,0603,X5R_2: CLABCONF0: =SB-COMEXmini
C77 = 100nF,_10V,_X7R,_10%,_0402_16: CLABCONF0: =SB-COMEXmini
C78 = 33pF,50V,NPO,10%,0402: CLABCONF0: =SB-COMEXmini
C79 = 33pF,50V,NPO,10%,0402_1: CLABCONF0: =SB-COMEXmini
C80 = 33pF,50V,NPO,10%,0402_2: CLABCONF0: =SB-COMEXmini
C81 = 100nF,_10V,_X7R,_10%,_0402_3: CLABCONF0: =SB-COMEXmini
FB3 = Ferrite_bead_,_30_Ohm@5A_2: CLABCONF0: =NOP
FB4 = Ferrite_bead_,_30_Ohm@5A_3: CLABCONF0: =SB-COMEXmini
FB5 = Ferrite_bead_,_30_Ohm@5A: CLABCONF0: =NOP
FB6 = Ferrite_bead_,_30_Ohm@5A_1: CLABCONF0: =SB-COMEXmini
P4 = Conn_1.,Half_MINI_PCIe_-PAD: CLABCONF0: 182K05201S=SB-COMEXmini / =SB-COMEXT10
P4A1 P5D1 P6C1 = PAD_mPCIE: CLABCONF0: =NOP
P4B1 P5C1 P6D1 = PAD_mPCIE: CLABCONF0: 383B52520S=SB-COMEXmini
P5 P6 = Conn,mini_PCIe_-PAD_0: CLABCONF0: 182K05201S=SB-COMEXmini / =SB-COMEXT10
P5A1 P5B1 P6A1 P6B1 = PAD_mPCIE
P8 = Conn.,_SATA_-_Rec,_15+7,_Vert: CLABCONF0: =SB-COMEXmini; P/N: 180K02200S
R33 = 0R,_0402_3: CLABCONF0: =NOP
R34 = 0R,_0402_6: CLABCONF0: =NOP
R35 = 0R,_0402_1: CLABCONF0: =SB-COMEXmini
R36 = 0R,_0402: CLABCONF0: =SB-COMEXmini
R37 = 0R,_0402_5: CLABCONF0: =SB-COMEXmini
R38 = 0R,_0402_8: CLABCONF0: =SB-COMEXmini
R39 = 0R,_0402_2: CLABCONF0: =SB-COMEXmini
R23 R40 = 0R,_0402_4: CLABCONF0: =SB-COMEXmini
R42 = 0R,_0402_7: CLABCONF0: =SB-COMEXmini
RN7 = RN,0R,8P4R@0805: CLABCONF0: =SB-COMEXmini
U12 = uSIM_SOCKET_0: CLABCONF0: =SB-COMEXmini
C39 = 100nF,_10V,_X7R,_10%,_0402_7: CLABCONF0: =SB-COMEXmini; Group: Front Panel
C42 = 10nF,_25V,_X7R,_10%,_0402_1: CLABCONF0: =SB-COMEXmini
C43 = 100nF,_10V,_X7R,_10%,_0402_3: CLABCONF0: =SB-COMEXmini; Group: Front Panel
C46 = 10nF,_25V,_X7R,_10%,_0402: CLABCONF0: =SB-COMEXmini
C47 = 100nF,_10V,_X7R,_10%,_0402_4: CLABCONF0: =SB-COMEXmini; Group: COM2
C48 = 100nF,_10V,_X7R,_10%,_0402_1: CLABCONF0: =SB-COMEXmini; Group: COM2
C49 = 100nF,_10V,_X7R,_10%,_0402_2: CLABCONF0: =SB-COMEXmini; Group: COM2
C50 = 100nF,_10V,_X7R,_10%,_0402: CLABCONF0: =SB-COMEXmini; Group: COM2
C51 = 100nF,_10V,_X7R,_10%,_0402_6: CLABCONF0: =SB-COMEXmini; Group: COM2
C52 = 100nF,_10V,_X7R,_10%,_0402_5: CLABCONF0: =SB-COMEXmini; Group: COM2
FB1 = Ferrite_bead_,_120_Ohm@3A_1: CLABCONF0: =SB-COMEXmini
FB2 = Ferrite_bead_,_120_Ohm@3A: CLABCONF0: =SB-COMEXmini
J1 = USB3_TYPEA_CONNECTER: CLABCONF0: =SB-COMEXmini; Manuf: MainSuper; Manuf PN: AK2SA009K1; PART_NUMBER: DS PORT2; TI_Silktext: DS PORT2
L1-L5 = USB_CHOKE_SGL: CLABCONF0: =SB-COMEXmini; Group: Front Panel
L6 L7 = EMI,_USB3_CHOKE: CLABCONF0: 142D11801S=SB-COMEXmini
P2 = Ultra_Mini_Serial_Connector: CLABCONF0: =SB-COMEXmini
P3 = microSD_push-pull: CLABCONF0: =SB-COMEXmini
R20 = 0R,_0402_2: CLABCONF0: =NOP
R21 = 0R,_0402: CLABCONF0: =NOP
R22 = 0R,_0402_3: CLABCONF0: =SB-COMEXmini
R24 = 68.1K_1%,_0402: CLABCONF0: =SB-COMEXmini
R25 = 68.1K_1%,_0402_1: CLABCONF0: =SB-COMEXmini
R26 = 0R,_0402_5: CLABCONF0: =NOP
R27 = 0R,_0402_1: CLABCONF0: =NOP
R30 = 10K,1%,0402,1_16W_1: CLABCONF0: =NOP
R31 = 4.99K,1%,0402,1_16W: CLABCONF0: =SB-COMEXmini
R32 = 4.99K,1%,0402,1_16W_1: CLABCONF0: =SB-COMEXmini
R107 = 2.21k_1%_0402: CLABCONF0: =SB-COMEXmini
R108 = 2.21k_1%_0402_1: CLABCONF0: =SB-COMEXmini
U4 U5 = RT9703,3A_Power_switch+FLG: CLABCONF0: =SB-COMEXmini
U6 = MAX3221_RS-232_1T1R_3_0.3V_XCVR: CLABCONF0: =SB-COMEXmini; Group: COM2
U7 U8 = USB_A-TYPE_DOUBLE_TH: CLABCONF0: =SB-COMEXmini; Group: Front Panel
U9-U11 = IC,ESD_Diode,0.25pF_,x4: CLABCONF0: =SB-COMEXmini

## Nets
+3.3V_AUX: FB3.1 FB4.1 P5.24(+3.3V_AUX)
+3.3V_S_PCIE: C63.2 C64.2 C65.2 C66.2 FB5.1 FB6.1 P5.2(+3.3V_1) P5.39(RSVD6) P5.41(RSVD7) P5.52(+3.3V_2)
+V1.5A_LAN2: C28.2 C33.2 C36.2 U3.39(VDD1p5_OUT_/_AUX_PWR_/_JTAG_CLK) U3.47(VDD1p5_2_/_AVDD1p9) U3.56(VDD1p5_1/_AVDD1p9)
+V1.5S: C82.2 C83.1 FB15.2 FB20.2 U15.9(DVDD_IO)
+V1.5S_PCIE: C54.2 C55.2 C56.2 C57.2 C58.2 C59.2 C61.2 C62.2 C71.2 C73.2 FB15.1 P4.6(+1.5V_1) P4.28(+1.5V_2) P4.48(+1.5V_3) P5.6(+1.5V_1) P5.28(+1.5V_2) P5.48(+1.5V_3) P6.6(+1.5V_1) P6.28(+1.5V_2) P6.48(+1.5V_3) ; also on sheet 8
+V3.3A: C1.1 C4.1 C10.2 C11.2 C12.2 C13.2 C14.2 C15.1 C19.2 C23.2 C29.2 C32.2 C37.2 C67.2 C68.2 C69.2 C70.2 FB3.2 FB6.2 OSC1.1(EN) OSC1.4(VCC) P1.P12(LED1_A) P1.P14(LED2_A) P4.2(+3.3V_1) P4.24(+3.3V_AUX) P4.39(RSVD6) P4.41(RSVD7) P4.52(+3.3V_2) P11.P12(LED1_A) P11.P14(LED2_A) R1.2 R2.1 R7.2 RN1.1(RA1) RN1.2(RB1) RN1.3(RC1) RN3.5(RD2) RN3.6(RC2) RN3.7(RB2) RN3.8(RA2) U1.3(SB3V) U3.1(LAN_PWR_GD_/_AVDD3p3) U3.10(VDD3p3) U3.27(VDD3p3_1_/_VDD1p0) U3.41(VDD3p3_2_/_VDD1p0) U3.51(VDD3p3_/_AVDD1p9) U3.64(VDD3p3_/_CTRL19) ; also on sheet 8 9 10
+V3.3A_SPI: P12.A91(SPI_POWER) ; also on sheet 9
+V3.3S: C2.1 C3.1 C5.1 C6.1 C7.1 C8.1 C47.1 C52.1 C53.2 C60.2 C72.2 C74.2 C75.2 C76.2 C84.2 DS1.A(ANODE) DS2.A(ANODE) DS3.A(ANODE) FB4.2 FB5.2 FB9.1 FB20.1 P3.4(VDD) P6.2(+3.3V_1) P6.24(+3.3V_AUX) P6.39(RSVD6) P6.41(RSVD7) P6.52(+3.3V_2) P8.8(V33) P8.9(V33) P8.10(V33/PC) Q9.2(G1) R15.1 R30.1 R41.1 U1.8(VCC) U1.23(VCC) U1.28(VCC) U6.15(VCC3) ; also on sheet 8 11 12
+V3.3S_AUD: C91.2 C92.1 FB9.2 U15.1(DVDD)
+V5A: C39.1 C40.2 C43.1 C44.2 FB1.1 FB2.1 ; also on sheet 8
+V5S: C81.2 FB8.2 P8.14(V5/PC) P8.15(V5) P8.16(V5) Q9.5(G2) R107.2 R108.2 ; also on sheet 8 11
+VBATA: C111.1 C112.1 P12.A104(VCC_12V) P12.A105(VCC_12V) P12.A106(VCC_12V) P12.A107(VCC_12V) P12.A108(VCC_12V) P12.A109(VCC_12V) P12.B104(VCC_12V) P12.B105(VCC_12V) P12.B106(VCC_12V) P12.B107(VCC_12V) P12.B108(VCC_12V) P12.B109(VCC_12V) ; also on sheet 8
+VCC5_AUD: C85.1 C86.1 C87.2 C88.1 C89.1 C90.1 FB8.1 U15.25(AVDD1) U15.38(AVDD2)
+VDD0.9_LAN2: C9.2 C26.2 C27.2 C31.2 C35.2 U3.11(VDD0p9_/_VDD1p0) U3.32(VDD0p9_/_VDD3p3) U3.38(VDD0p9_OUT_/_JTAG_TMS) U3.42(VDD0p9_/_XTAL2) U3.59(VDD0p9_/_DIS_REG10)
AGND_HDA: C87.1 C88.2 C89.2 C93.2 C94.2 C97.2 C98.2 C103.2 C104.2 C105.1 C106.2 FB14.1 J2.1 R48.1 R49.2 U15.26(AVSS1) U15.42(AVSS2)
GND: C1.2 C2.2 C3.2 C4.2 C5.2 C6.2 C7.2 C8.2 C9.1 C10.1 C11.1 C12.1 C13.1 C14.1 C15.2 C19.1 C21.1 C23.1 C24.2 C26.1 C27.1 C28.1 C29.1 C30.2 C31.1 C32.1 C33.1 C35.1 C36.1 C37.1 C39.2 C40.1 C41.1 C42.2 C43.2 C44.1 C45.1 C46.2 C47.2 C50.2 C51.2 C52.2 C53.1 C54.1 C55.1 C56.1 C57.1 C58.1 C59.1 C60.1 C61.1 C62.1 C63.1 C64.1 C65.1 C66.1 C67.1 C68.1 C69.1 C70.1 C71.1 C72.1 C73.1 C74.1 C75.1 C76.1 C77.1 C78.2 C79.2 C80.2 C81.1 C82.1 C83.2 C84.1 C85.2 C86.2 C90.2 C91.1 C92.2 C107.1 C108.2 C109.2 C110.2 C111.2 C112.2 J1.4(GND) J1.7(GND) J1.SH1 J1.SH2 J2.2 L6.5 L6.6 L7.5 L7.6 OSC1.2(GND) P1.S1(SHIELD) P1.S2(SHIELD) P2.8 P2.9(CHASSIS) P2.10(CHASSIS) P2.11(CHASSIS) P2.12(CHASSIS) P3.6(VSS) P3.9(M1) P3.10(M2) P3.11(M3) P3.12(M4) P4.4(GND7) P4.9(GND1) P4.15(GND2) P4.18(GND8) P4.21(GND3) P4.26(GND9) P4.27(GND4) P4.29(GND5) P4.34(GND10) P4.35(GND6) P4.40(GND11) P4.50(GND12) P4.53(PAD1) P4.54(PAD2) P4A1.1(MECH) P4B1.1(MECH) P5.4(GND7) P5.9(GND1) P5.15(GND2) P5.18(GND8) P5.21(GND3) P5.26(GND9) P5.27(GND4) P5.29(GND5) P5.34(GND10) P5.35(GND6) P5.40(GND11) P5.50(GND12) P5.53(PAD1) P5.54(PAD2) P5.55(P5) P5.56(P6) P5A1.1(MECH) P5B1.1(MECH) P5C1.1(MECH) P5D1.1(MECH) P6.4(GND7) P6.9(GND1) P6.15(GND2) P6.18(GND8) P6.21(GND3) P6.26(GND9) P6.27(GND4) P6.29(GND5) P6.34(GND10) P6.35(GND6) P6.40(GND11) P6.50(GND12) P6.53(PAD1) P6.54(PAD2) P6.55(P5) P6.56(P6) P6A1.1(MECH) P6B1.1(MECH) P6C1.1(MECH) P6D1.1(MECH) P8.1(GND) P8.4(GND) P8.7(GND) P8.11(GND) P8.12(GND) P8.13(GND) P8.17(GND) P8.19(GND) P8.L1(SH) P8.L2(SH) P9.CN P10.CN P11.S1(SHIELD) P11.S2(SHIELD) P12.A1(GND_(FIXED)) P12.A11(GND_(FIXED)) P12.A21(GND_(FIXED)) P12.A31(GND_(FIXED)) P12.A41(GND_(FIXED)) P12.A51(GND_(FIXED)) P12.A57(GND) P12.A60(GND_(FIXED)) P12.A66(GND) P12.A70(GND_(FIXED)) P12.A80(GND_(FIXED)) P12.A90(GND_(FIXED)) P12.A100(GND_(FIXED)) P12.A110(GND_(FIXED)) P12.B1(GND_(FIXED)) P12.B11(GND_(FIXED)) P12.B21(GND_(FIXED)) P12.B31(GND_(FIXED)) P12.B41(GND_(FIXED)) P12.B51(GND_(FIXED)) P12.B60(GND_(FIXED)) P12.B70(GND_(FIXED)) P12.B80(GND_(FIXED)) P12.B90(GND_(FIXED)) P12.B100(GND_(FIXED)) P12.B110(GND_(FIXED)) P19.8 Q9.1(S1) Q9.4(S2) R12.2 R19.2 R24.2 R25.2 R31.2 R32.2 R51.2 RN1.4(RD1) RN4.5(RD2) RN4.6(RC2) RN4.7(RB2) U1.1(ATest) U1.2(GND) U1.6(TestI) U1.7(TestBI) U1.9(GND) U1.22(GND) U1.29(GND) U1.39(ATest) U1.40(ATest) U1.41(EP) U3.65(EPAD-GND) U4.4(GND) U5.4(GND) U6.1(EN) U6.14(GND) U7.4(GND) U7.8(GND) U7.9(SHIELD) U7.10(SHIELD) U7.11(SHIELD) U7.12(SHIELD) U8.4(GND) U8.8(GND) U8.9(SHIELD) U8.10(SHIELD) U8.11(SHIELD) U8.12(SHIELD) U9.3(Vn) U9.8(Vn) U10.3(Vn) U10.8(Vn) U11.3(Vn) U11.8(Vn) U12.5(GND) U12.9(NC9) U12.10(NC10) U12.11(NC11) U12.12(NC12) U14.3(Vn) U14.8(Vn) U15.7(DVSS) U16.3(Vn) U16.8(Vn) ; also on sheet 8 9 10 11 12
+VRTC: C110.1 P12.A47(VCC_RTC) ; also on sheet 8
AUD_OUT_L: C100.2 U15.35(FRONT-L)
AUD_OUT_R: C99.2 U15.36(FRONT-R)
AUD_SENSA: R45.1 R54.1 U15.13(Sense_A)
BIOS_DIS0#: P12.A34(BIOS_DIS0#) TP7.1
BIOS_DIS1#: P12.B88(BIOS_DIS1#) ; also on sheet 9
BUF_PLT_RST#: P4.22(PERST#) P5.22(PERST#) P6.22(PERST#) P12.B50(CB_RESET#) U1.20(LRESET#) U3.17(PE_RST_N) ; also on sheet 10
C1M: C49.2 U6.4(C1-)
C1P: C49.1 U6.2(C1+)
C2M: C48.2 U6.6(C2-)
C2P: C48.1 U6.5(C2+)
CBOT_LAN2: C34.1 U3.37(CBOT_/_VDD1p0)
CLK_LAN2: C38.1 R18.2 R19.1
CLK_LAN2_X1: C38.2 U3.46(XTAL1_/_ATESTN)
CLK_PCIE_N0: P5.11(REFCLK-) P12.A89(PCIE0_CK_REF-)
CLK_PCIE_N1: P4.11(REFCLK-) P12.B56(RSRVD)
CLK_PCIE_N2: P12.B53(RSRVD) U3.25(PECLKn)
CLK_PCIE_P0: P5.13(REFCLK+) P12.A88(PCIE0_CK_REF+)
CLK_PCIE_P1: P4.13(REFCLK+) P12.B55(RSRVD)
CLK_PCIE_P2: P12.B52(RSRVD) U3.26(PECLKp)
COM0_RX: Q12.4(S2) U6.9(R1OUT)
COM0_RX_RS232: P2.3 U6.8(R1IN)
COM0_TX: Q12.1(S1) U6.11(T1IN)
COM0_TX_RS232: P2.1 U6.13(T1OUT)
COM_RX_GT: Q12.5(G2) R107.1
COM_TX_GT: Q12.2(G1) R108.1
CTOP_LAN2: C34.2 U3.40(CTOP_/_JTAG_TDI)
DDI0_CLK_AUXP_IN: P12.B98(DDI0_CTRLCLK_AUX+) ; also on sheet 11
DDI0_DAT_AUXM_IN: P12.B99(DDI0_CTRLDAT_AUX-) ; also on sheet 11
DDI0_DDC_AUX_SEL: P12.B95(DDI0_DDC_AUX_SEL) ; also on sheet 11
DDI0_LANE0_N: P12.B72(DDI0_PAIR0-) ; also on sheet 11
DDI0_LANE0_P: P12.B71(DDI0_PAIR0+) ; also on sheet 11
DDI0_LANE1_N: P12.B74(DDI0_PAIR1-) ; also on sheet 11
DDI0_LANE1_P: P12.B73(DDI0_PAIR1+) ; also on sheet 11
DDI0_LANE2_N: P12.B76(DDI0_PAIR2-) ; also on sheet 11
DDI0_LANE2_P: P12.B75(DDI0_PAIR2+) ; also on sheet 11
DDI0_LANE3_N: P12.B82(DDI0_PAIR3-) ; also on sheet 11
DDI0_LANE3_P: P12.B81(DDI0_PAIR3+) ; also on sheet 11
DDIO_HPDET_IN: P12.B89(DDI0_HPD) ; also on sheet 11
DEV_OFF_LAN2#_PU: R15.2 U3.28(DEV_OFF_N)
DS1_C1: DS1.C1(CATHODE1) R3.1
DS1_C2: DS1.C2(CATHODE2) R9.1
DS2_C1: DS2.C1(CATHODE1) R4.1
DS2_C2: DS2.C2(CATHODE2) R5.1
DS3_C1: DS3.C1(CATHODE1) R6.1
DS3_C2: DS3.C2(CATHODE2) R8.1
eDP_AUXN_I2C_DAT: P12.A84(LVDS_I2C_DAT) ; also on sheet 12
eDP_AUXP_I2C_CK: P12.A83(LVDS_I2C_CK) ; also on sheet 12
eDP_HPD_IN: P12.A87(eDP_HPD) ; also on sheet 12
eDP_LVDS_BKCTL: P12.B83(LVDS_BKLT_CTRL) ; also on sheet 12
eDP_LVDS_BKEN: P12.B79(LVDS_BKLT_EN) ; also on sheet 12
eDP_LVDS_VDDEN: P12.A77(LVDS_VDD_EN) ; also on sheet 12
eDP_N0_A2-: P12.A76(LVDS_A2-) ; also on sheet 12
eDP_N1_A1-: P12.A74(LVDS_A1-) ; also on sheet 12
eDP_N2_A0-: P12.A72(LVDS_A0-) ; also on sheet 12
eDP_N3_CK-: P12.A82(LVDS_A_CK-) ; also on sheet 12
eDP_P0_A2+: P12.A75(LVDS_A2+) ; also on sheet 12
eDP_P1_A1+: P12.A73(LVDS_A1+) ; also on sheet 12
eDP_P2_A0+: P12.A71(LVDS_A0+) ; also on sheet 12
eDP_P3_CK+: P12.A81(LVDS_A_CK+) ; also on sheet 12
GEN_PU: R41.2 U6.12(FORCEON) U6.16(FORCEOFF)
HDA_BITCLK: P12.A32(AC_BITCLK) RN8.2(RB1)
HDA_BITCLK_T: RN8.7(RB2) U15.6(BIT-CLK)
HDA_REF_PD: R51.1 U15.40(JDREF)
HDA_REFFLT: C105.2 C106.1 U15.27(VREF)
HDA_RST#: P12.A30(AC_RST#) RN8.4(RD1)
HDA_RST#_T: RN8.5(RD2) U15.11(RESET#)
HDA_SDATAOUT: P12.A33(AC_SDOUT) RN8.1(RA1)
HDA_SDATAOUT_T: RN8.8(RA2) U15.5(SDATA-OUT)
HDA_SDIN0: P12.B30(AC_SDIN0) R50.2
HDA_SDIN0_T: R50.1 U15.8(SDATA-IN)
HDA_SYNC: P12.A29(AC_SYNC) RN8.3(RC1)
HDA_SYNC_T: RN8.6(RC2) U15.10(SYNC)
HOUTB_L: C93.1 FB11.2 P9.4(L) U14.2(CH2) U14.9(NC)
HOUTB_L1: C100.1 FB11.1
HOUTB_R: C94.1 FB10.2 P9.3(R) U14.1(CH1) U14.10(NC)
HOUTB_R1: C99.1 FB10.1
I2C0_SCL_GPIO79: P12.B33(I2C_CK) P19.2
I2C0_SDA_GPIO78: P12.B34(I2C_DAT) P19.4
LAN1_CT1: C107.2 C108.1 P11.P5(CT)
LAN1_CT2: C109.1 P11.P6(CT)
LAN1_MDIN0: P11.P2(MDI0-) P12.A12(GBE0_MDI0-)
LAN1_MDIN1: P11.P4(MDI1-) P12.A9(GBE0_MDI1-)
LAN1_MDIN2: P11.P8(MDI2-) P12.A6(GBE0_MDI2-)
LAN1_MDIN3: P11.P10(MDI3-) P12.A2(GBE0_MDI3-)
LAN1_MDIP0: P11.P1(MDI0+) P12.A13(GBE0_MDI0+)
LAN1_MDIP1: P11.P3(MDI1+) P12.A10(GBE0_MDI1+)
LAN1_MDIP2: P11.P7(MDI2+) P12.A7(GBE0_MDI2+)
LAN1_MDIP3: P11.P9(MDI3+) P12.A3(GBE0_MDI3+)
LAN2_CT1: C21.2 C24.1 P1.P5(CT)
LAN2_CT2: C30.1 P1.P6(CT)
LAN2_JTAG_TCK: RN1.7(RB2) U3.19(JTAG_CLK_/_VDD1p9)
LAN2_JTAG_TDO: RN1.6(RC2) U3.4(JTAG_TDO_/_VDD1p0)
LAN2_JTAG_TMS: RN1.8(RA2) U3.18(JTAG_TMS_/_VDD1p0)
LAN2_MDIN0: P1.P2(MDI0-) U3.57(MDI_M[0])
LAN2_MDIN1: P1.P4(MDI1-) U3.54(MDI_M[1])
LAN2_MDIN2: P1.P8(MDI2-) U3.52(MDI_M[2])
LAN2_MDIN3: P1.P10(MDI3-) U3.49(MDI_M[3])
LAN2_MDIP0: P1.P1(MDI0+) U3.58(MDI_P[0])
LAN2_MDIP1: P1.P3(MDI1+) U3.55(MDI_P[1])
LAN2_MDIP2: P1.P7(MDI2+) U3.53(MDI_P[2])
LAN2_MDIP3: P1.P9(MDI3+) U3.50(MDI_P[3])
LED6_WW#: P4.42(LED_WWAN#) R37.1
LED7_WW#: P5.42(LED_WWAN#) R35.1
LED_3.3VS: Q9.6(D1) R9.2
LED_5VS: Q9.3(D2) R8.2
LED_BT#: R5.2 R39.2 R40.2
LED_WLAN#: R3.2 R36.2 R38.2
LED_WWAN#: R4.2 R35.2 R37.2
LEDP6_BT#: P4.46(LED_WPAN#) R40.1
LEDP6_WLAN#: P4.44(LED_WLAN#) R38.1
LEDP7_BT#: P5.46(LED_WPAN#) R39.1
LEDP7_WLAN#: P5.44(LED_WLAN#) R36.1
LINC_100_LAN1: P12.A4(GBE0_LINK100#) R56.1
LINC_100_LAN2: R11.1 U3.31(LED0)
LINC_1000_LAN1: P12.A5(GBE0_LINK1000#) R55.1
LINC_1000_LAN2: R10.1 U3.33(LED2)
LINC_ACT_LAN1: P12.B2(GBE0_ACT#) R57.1
LINC_ACT_LAN2: R13.1 U3.30(LED1)
LINC_L: C103.1 FB13.2 P10.4(L) U16.4(CH3) U16.7(NC)
LINC_R: C104.1 FB12.2 P10.3(R) U16.2(CH2) U16.9(NC)
LPC_AD0: P12.B4(LPC_AD0) U1.30(LAD0) ; also on sheet 10
LPC_AD1: P12.B5(LPC_AD1) U1.27(LAD1) ; also on sheet 10
LPC_AD2: P12.B6(LPC_AD2) U1.24(LAD2) ; also on sheet 10
LPC_AD3: P12.B7(LPC_AD3) U1.21(LAD3) ; also on sheet 10
LPC_CLK: P12.B10(LPC_CLK) U1.25(LCLK) ; also on sheet 10
LPC_FRAME#: P12.B3(LPC_FRAME#) U1.26(LFRAME#) ; also on sheet 10
LPC_SERIRQ#: P12.A50(LPC_SERIRQ) U1.37(SERIRQ)
LPCPD#: R2.2 U1.38(LPCPD#)
LVDS_A3+: P12.A78(LVDS_A3+) ; also on sheet 12
LVDS_A3-: P12.A79(LVDS_A3-) ; also on sheet 12
MIC_INT_L: C102.1 U15.21(MIC1-L)
MIC_INT_R: C101.1 U15.22(MIC1-R)
MIC_L: C102.2 FB13.1 R53.2
MIC_R: C101.2 FB12.1 R52.2
MIC_VREF_L: R53.1 U15.28(MIC1-VREFO-L)
MIC_VREF_R: R52.1 U15.32(MIC1-VREFO-R)
OC#1_2_HB: P12.A44(USB_2_3_OC#) R27.1
OSC_CLK25: OSC1.3(OUT) R18.1
P11_LED_LAN1: P11.P11(LED1_C) R55.2 R56.2
P11_LED_LAN2: P1.P11(LED1_C) R10.2 R11.2
P13_LED_LAN1: P11.P13(LED2_C) R57.2
P13_LED_LAN2: P1.P13(LED2_C) R13.2
P15_1: FB14.2 P9.1(COM) P10.1(COM)
PCIE_RN_LAN2: C22.1 U3.20(PE_Tn)
PCIE_RP_LAN2: C25.1 U3.21(PE_Tp)
PCIE_RXN0: P5.23(PER_N0) P12.B69(PCIE_RX0-)
PCIE_RXN1: P4.23(PER_N0) P12.B65(PCIE_RX1-)
PCIE_RXN2: C22.2 P12.B62(PCIE_RX2-)
PCIE_RXP0: P5.25(PER_P0) P12.B68(PCIE_RX0+)
PCIE_RXP1: P4.25(PER_P0) P12.B64(PCIE_RX1+)
PCIE_RXP2: C25.2 P12.B61(PCIE_RX2+)
PCIE_TXN0: P5.31(PET_N0) P12.A69(PCIE_TX0-)
PCIE_TXN1: P4.31(PET_N0) P12.A65(PCIE_TX1-)
PCIE_TXN2: P12.A62(PCIE_TX2-) U3.23(PE_Rn)
PCIE_TXP0: P5.33(PET_P0) P12.A68(PCIE_TX0+)
PCIE_TXP1: P4.33(PET_P0) P12.A64(PCIE_TX1+)
PCIE_TXP2: P12.A61(PCIE_TX2+) U3.24(PE_Rp)
PCIE_WAKE#: P4.1(WAKE#) P5.1(WAKE#) P12.B66(WAKE0#) U3.16(PE_WAKE_N_/_JTAG_TDO)
PM_CLKRUN#: R1.1 U1.19(CLKRUN#)
PWRBTN#: P12.B12(PWRBTN#) ; also on sheet 8
RSET_LAN2: R12.1 U3.48(RSET)
RSVD2_PD_LAN2: RN4.3(RC1) U3.2(RSVD2_PD)
RSVD3_PD_LAN2: RN4.2(RB1) U3.3(RSVD3_PD)
RSVD5_PU_LAN2: RN3.4(RD1) U3.5(RSVD5_PU_/)
RSVD6_PU_LAN2: RN3.3(RC1) U3.6(RSVD6_PU)
RSVD7_PD_LAN2: R7.1 RN4.4(RD1) U3.7(RSVD7_PU)
RSVD8_PU_LAN2: RN3.2(RB1) U3.8(RSVD8_PU)
RSVD9_PU_LAN2: RN3.1(RA1) U3.9(RSVD9_PU)
SATA_LED#: P12.A28(ATA_ACT#) R6.2
SATA_RXN0: P6.25(PER_P0) P12.A20(SATA0_RX-)
SATA_RXN1: P8.5(RXN) P12.B20(SATA1_RX-)
SATA_RXP0: P6.23(PER_N0) P12.A19(SATA0_RX+)
SATA_RXP1: P8.6(RXP) P12.B19(SATA1_RX+)
SATA_TXN0: P6.31(PET_N0) P12.A17(SATA0_TX-)
SATA_TXN1: P8.3(TXN) P12.B17(SATA1_TX-)
SATA_TXP0: P6.33(PET_P0) P12.A16(SATA0_TX+)
SATA_TXP1: P8.2(TXP) P12.B16(SATA1_TX+)
SDIO_CD#_GPIO38: P12.B63(GPO3/SD_CD) P19.7 R31.1
SDIO_WP_GPIO7: P12.B57(GPO2/SD_WP) P19.6 R32.1
SENSE_PORTB: P10.CO R54.2 U16.1(CH1) U16.10(NC)
SENSE_PORTD: P9.CO R45.2 U14.4(CH3) U14.7(NC)
SIM_CLK: C80.1 RN7.1(RA1) U12.3(CLK)
SIM_CLK_P4: P5.12(RSVD15) RN7.8(RA2)
SIM_IO: C79.1 RN7.3(RC1) U12.7(IO)
SIM_IO_P4: P5.10(RSVD14) RN7.6(RC2)
SIM_RST: C78.1 RN7.4(RD1) U12.2(RST)
SIM_RST_P4: P5.14(RSVD16) RN7.5(RD2)
SIM_VCC: C77.2 R42.1 U12.1(VCC)
SIM_VCC_P4: P5.8(RSVD13) R42.2
SIM_VPP: RN7.2(RB1) U12.6(VPP)
SIM_VPP_P4: P5.16(RSVD17) RN7.7(RB2)
SLOT3_SDIO_CLK: P3.5(CLK) P12.A93(GPO0/SD_CLK)
SLOT3_SDIO_CMD: P3.3(CMD) P12.B54(GPO1/SD_CMD) R30.2
SLOT3_SDIO_D0: P3.7(DAT0) P12.A54(GPI0/SD_D0)
SLOT3_SDIO_D1: P3.8(DAT1) P12.A63(GPI1/SD_D1)
SLOT3_SDIO_D2: P3.1(DAT2) P12.A67(GPI2/SD_D2)
SLOT3_SDIO_D3: P3.2(DAT3/CD) P12.A85(GPI3/SD_D3)
SLP_S3#: P12.A15(SUS_S3#) ; also on sheet 8
SLP_S4#: P12.A18(SUS_S4#) R22.1 R23.1
SMB_CLK: P12.B13(SMB_CK) P19.1 R33.2
SMB_CLK_PCIE: P4.30(SMB_CLK) P5.30(SMB_CLK) R33.1
SMB_DATA: P12.B14(SMB_DAT) P19.3 R34.2
SMB_DATA_PCIE: P4.32(SMB_DATA) P5.32(SMB_DATA) R34.1
SPDI_INT: C96.1 R47.1
SPDI_RLT: R47.2 U15.47(SPDIFI/EAPD)
SPDIF_IN: C96.2 C97.1 P10.2(AUX) R49.1 U16.5(CH4) U16.6(NC)
SPDIF_OUT: C98.1 P9.2(AUX) R46.2 R48.2 U14.5(CH4) U14.6(NC)
SPDO_RLT: C95.1 U15.48(SPDIFO)
SPDO_RLT_INT: C95.2 R46.1
SPI_B_CLK: P12.A94(SPI_CLK) ; also on sheet 9
SPI_B_CS0#: P12.B97(SPI_CS#) ; also on sheet 9
SPI_B_MISO: P12.A92(SPI_MISO) ; also on sheet 9
SPI_B_MOSI: P12.A95(SPI_MOSI) ; also on sheet 9
SSRXM0L: J1.5(SSRXN) L6.1
SSRXP0L: J1.6(SSRXP) L6.2
SSTXM0L: J1.8(SSTXN) L7.1
SSTXP0L: J1.9(SSTXP) L7.2
SYS_RST#_IN: P12.B49(SYS_RESET#) ; also on sheet 8
TEST1#: P12.A86(RSRVD) ; also on sheet 9
TEST_EN_PD_LAN2: RN1.5(RD2) U3.29(JTAG_TDI__/_TEST_EN)
UART0_RXD: P12.A99(SER0_RX) Q12.3(D2)
UART0_TXD: P12.A98(SER0_TX) Q12.6(D1)
USB1_OC#: P12.A38(USB_6_7_OC#) R26.1
USB1N_T: L1.3 U7.2(D-) U9.2(CH2) U9.9(NC)
USB1P_T: L1.2 U7.3(D+) U9.1(CH1) U9.10(NC)
USB2_PN0: J1.2(DM) L5.3 U11.5(CH4) U11.6(NC)
USB2_PP0: J1.3(DP) L5.2 U11.4(CH3) U11.7(NC)
USB2N_T: L3.3 U7.6(D-) U9.5(CH4) U9.6(NC)
USB2P_T: L3.2 U7.7(D+) U9.4(CH3) U9.7(NC)
USB3_RXN0: L6.4 P12.A22(USB_SSRX0-)
USB3_RXP0: L6.3 P12.A23(USB_SSRX0+)
USB3_TXN0: L7.4 P12.B22(USB_SSTX0-)
USB3_TXP0: L7.3 P12.B23(USB_SSTX0+)
USB12_PWREN: R20.1 R22.2 U4.5(EN)
USB12RSET: R24.1 U4.8(IP)
USB34_PWREN: R21.1 R23.2 U5.5(EN)
USB34RSET: R25.1 U5.8(IP)
USB_OC#_12: R26.2 U4.1(FLG)
USB_OC#_34HB: R27.2 U5.1(FLG)
USB_PN0: L5.4 P12.A45(USB0-)
USB_PN1: L1.4 P12.B45(USB1-)
USB_PN2: L3.4 P12.A36(USB6-)
USB_PP0: L5.1 P12.A46(USB0+)
USB_PP1: L1.1 P12.B46(USB1+)
USB_PP2: L3.1 P12.A37(USB6+)
USB_VCC12: C41.2 C42.1 J1.1(VBUS) U4.2(Vout) U4.3(Vout) U7.1(VBUS) U7.5(VBUS)
USB_VCC34: C45.2 C46.1 U5.2(Vout) U5.3(Vout) U8.1(VBUS) U8.5(VBUS)
USBF12: FB1.2 R20.2 U4.6(Vin) U4.7(Vin)
USBF34: FB2.2 R21.2 U5.6(Vin) U5.7(Vin)
USBH1N_T: L2.3 U8.2(D-) U10.2(CH2) U10.9(NC)
USBH1P_T: L2.2 U8.3(D+) U10.1(CH1) U10.10(NC)
USBH2N_T: L4.3 U8.6(D-) U10.5(CH4) U10.6(NC)
USBH2P_T: L4.2 U8.7(D+) U10.4(CH3) U10.7(NC)
USBH_PN1: L2.4 P12.A42(USB2-)
USBH_PN2: L4.4 P12.B42(USB3-)
USBH_PN3: P5.36(USB_D-) P12.A39(USB4-)
USBH_PN4: P4.36(USB_D-) P12.B39(USB5-)
USBH_PP1: L2.1 P12.A43(USB2+)
USBH_PP2: L4.1 P12.B43(USB3+)
USBH_PP3: P5.38(USB_D+) P12.A40(USB4+)
USBH_PP4: P4.38(USB_D+) P12.B40(USB5+)
VM: C50.1 U6.7(V-)
VP: C51.1 U6.3(V+)
WDT_GPIO10#_S5: P12.B27(WDT) P19.5

Not connected (* = marked no-connect by the designer): P2 2* 4* 5* 6* 7*; P4 3(RSVD1)* 5(RSVD2)* 7(CLKREQ#)* 8(RSVD13)* 10(RSVD14)* 12(RSVD15)* 14(RSVD16)* 16(RSVD17)* 17(RSVD3)* 19(RSVD4)* 20(RSVD18)* 37(RSVD5)* 43(RSVD8)* 45(RSVD9)* 47(RSVD10)* 49(RSVD11)* 51(RSVD12)*; P5 3(RSVD1)* 5(RSVD2)* 7(CLKREQ#)* 17(RSVD3)* 19(RSVD4)* 20(RSVD18)* 37(RSVD5)* 43(RSVD8)* 45(RSVD9)* 47(RSVD10)* 49(RSVD11)* 51(RSVD12)*; P6 1(WAKE#)* 3(RSVD1)* 5(RSVD2)* 7(CLKREQ#)* 8(RSVD13)* 10(RSVD14)* 11(REFCLK-)* 12(RSVD15)* 13(REFCLK+)* 14(RSVD16)* 16(RSVD17)* 17(RSVD3)* 19(RSVD4)* 20(RSVD18)* 30(SMB_CLK)* 32(SMB_DATA)* 36(USB_D-)* 37(RSVD5)* 38(USB_D+)* 42(LED_WWAN#)* 43(RSVD8)* 44(LED_WLAN#)* 45(RSVD9)* 46(LED_WPAN#)* 47(RSVD10)* 49(RSVD11)* 51(RSVD12)*; P8 18(DAS/DSS)* 20(V12/PC)* 21(V12)* 22(V12)*; P12 A8(GBE0_LINK#) A14(GBE0_CTREF)* A24(SUS_S5#)* A25(USB_SSRX1-)* A26(USB_SSRX0+)* A27(BATLOW#)* A35(THRMTRIP#) A48(EXCD0_PERST#)* A49(EXCD0_CPPE#)* A52(RSRVD)* A53(RSRVD)* A55(RSRVD)* A56(RSRVD)* A58(PCIE_TX3+)* A59(PCIE_TX3-)* A96(TPM_PP)* A97(TYPE10#)* A101(SER1_TX)* A102(SER1_RX)* A103(LID#)* B8(LPC_DRQ0#)* B9(LPC_DRQ1#)* B15(SMB_ALERT#)* B18(SUS_STAT#)* B24(PWR_OK)* B25(USB_SSTX1-)* B26(USB_SSTX1+)* B28(AC_SDIN2)* B29(AC_SDIN1)* B32(SPKR)* B35(THRM#)* B36(USB7-)* B37(USB7+)* B38(USB_4_5_OC#)* B44(USB_0_1_OC#)* B47(EXCD1_PERST#)* B48(EXCD1_CPPE#)* B58(PCIE_RX3+)* B59(PCIE_RX3-)* B67(WAKE1#)* B77(DDI0_PAIR4+)* B78(DDI0_PAIR4-)* B84(VCC_5V_SBY)* B85(VCC_5V_SBY)* B86(VCC_5V_SBY)* B87(VCC_5V_SBY)* B91(DDI0_PAIR5+)* B92(DDI0_PAIR5-)* B93(DDI0_PAIR6+)* B94(DDI0_PAIR6-)* B96(USB_HOST_PRSNT)* B101(FAN_PWMOUT)* B102(FAN_TACHIN)* B103(SLEEP#)*; RN4 1(RA1) 8(RA2); U1 4(GPIO6)* 5(NC)* 10(NBO)* 11(NBO)* 12(NBO)* 13(NBO)* 14(NBO)* 15(NBO)* 16(NBO)* 17(NBO)* 18(NBO)* 31(NBO)* 32(NBO)* 33(NBO)* 34(NBO)* 35(NBO)* 36(NBO)*; U3 12(RSVD12_PU_/__NVM_SI)* 13(RSVD13_PU_/_NVM_SK)* 14(RSVD14_PU_/__NVM_SO)* 15(RSVD15_PU_/_NVM_CS_N)* 22(NC_/_AVDD1p9)* 34(RSVD34_PU)* 35(RSVD35_PU)* 36(RSVD36_PU)* 43(RSVD43_/_XTAL1)* 44(RSVD44_/__AVDD19)* 45(XTAL2_/_ATEST_P)* 60(SDP3_/_VDD1p0)* 61(SDP1[PCIe_DIS]__/_AVDD1p9)* 62(SDP2_/_CTRL10)* 63(SDP0_/_AVDD1p9)*; U6 10(INVALID)*; U11 1(CH1) 2(CH2) 9(NC)* 10(NC)*; U12 4(NC4)* 8(NC8)*; U15 2(SPDIFO2)* 3(GPIO0_DMCLK)* 4(GPIO1_DMICDATA)* 12(PCBEEP) 14(LINE2-L)* 15(LINE2-R)* 16(MIC2-L)* 17(MIC2-R)* 18(CD-L)* 19(CD-GND)* 20(CD-R)* 23(LINE1-L)* 24(LINE1-R)* 29(LINE1-VREFO)* 30(MIC2-VREFO)* 31(LINE2-VREFO)* 33(Sense_C)* 34(Sense_B)* 37(VREFO)* 39(SURR-L)* 41(SURR-R)* 43(CEN)* 44(LFE)* 45(SIDESURR-L)* 46(SIDESURR-R)*

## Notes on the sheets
sheet 1
- SB-COMEXmini Rev. 1.1
- 5V
- POWER
  CIRC.
- 3.3V
- RTC
  Batt.
- PG 08
- 1.5V
- PAGE
- FUNCTION
- Rev 1.1
- RTC
- SMBUS
- SMBus
- GPIO / MISC
  HDR 2x5
- 01
- INDEX
- SPI
- SPI FLASH
  ( DEBUG )
- GPIOs
- SPI
- PG 07
- GPIO
- PG 09
- 02
- LAN1 CORE & TPM & LED
- MDI
- CORE  LAN GIGABIT
- RJ45
  conn.
- HDMI
  conn.
- DDI0
- LAN  MDI
- 03
- LAN2- I211
- DDI0
- PG 02
- PG 11
- 04
- USB2.0 & SD
- PG 12
- DDI1 / LVDS
- DP
  conn.
- LVDS
  BYPASS
- DDI1
- PCIEx1
- PCIE x1
- PCIE  LAN GIGABIT
- RJ45
  conn.
- x1
- PG 03
- 05
- MINI PCIE & MSATA & SATA
- PG 12
- PG 03
- LVDS
- SIM
  conn.
- LVDS 24 bit
  40 pin FPC
- LVDS CTRL.
- LVDS CTRL.
- PCIEx1
- PCIE x1
- mini PCIE connector FULL
- 06
- HD AUDIO
- PG 12
- x1
- PG 05
- PG 05
- COMEX-IE38
  COM EXPRESS 2.0
  TYPE 10
- 07
- EXTENSION SLOTS
- USB 2.0
- SMB
- PG 05
- SATA II
- SATA + POWER CONN.
- SATA 1
- 08
- POWER
- PCIEx1
- PCIE x1
- mini PCIE connector HALF
- x1
- PG 05
- SATA II
- SATA 0
- 09
- SPI BIOS & EC (DEBUG)
- mSATA
- PG 05
- USB 2.0
- SMB
- Available only when SSD isn't assembled
- SDIO
- SDIO
- 10
- PORT80 (DEBUG)
- uSD SLOT
- PG 04
- 3.5"
  AUDIO IN
  SPDIF/N IN
- PG 06
- 11
- HDMI PORT(DDI0)
- ALC888/886
- HDA
- USB2.0
- USB 2.0
- USB2
  x2
- HDA
- USB 2.0
- 3.5"
  AUDIO OUT
  SPDIF/N OUT
- PG 06
- 12
- DISPLAY PORT (DDI1)
- PG 06
- PG 04
- USB3.0
- USB 3.0
- USB3
  x1
- USB2.0
- USB 2.0
- USB 2.0
- USB2
  x2
- PG 04
- USB2.0
- USB 2.0
- PG 04
- LPC
- UART
- RS232
  DRIVER
- PG 04
- PORT80
  DEBUG
- TPM
- UART
  RX/TX
- PG 10
- PG 02
- PG 04
sheet 2
- MISC
- TPM
- LPC
- GBE LAN
- MISC
- NP
- NP
sheet 3
- GIGABIT LAN2
- NP
- NP
- PCIE 2
- I211
sheet 4
- USB PORT 1 & 2
- USB PORT HUB 1 & 2
- COM PORT
- NP
- NP
- NP
- NP
- UART 0
- SD CARD
- TO CHECK SDIO PWR SWITCHING
- NP
- SD CARD
- USB (ext conn.)
- USB (ext conn.)
- USB (int. conn.)
- MISC
- USB3
sheet 5
- MINI PCIE SOCKET
- PCIE2
  MINI PCIE SOCKET
- SMBus
- max 1A
- max 1A
- max 1A
- max 0.5A
- NP
- max 0.5A
- max 0.5A
- max 0.33A
- max 0.33A
- max 0.33A
- PCIE CLK
- NP
- MINI PCIE
- SATA 0
- NP
- PCIE 1
- micro SIM option
- SATA /
  MINI PCIE SOCKET
- SATA HDD
- SATA1
- max 0.33A
- SATA0
- mSATA0 -3Gb/s
  Available only when on-module iSSD isn't populated
- USB (int. conn.)
- MISC
sheet 6
- HIGH DEFINITION AUDIO CODEC
- SENSA:
  PORT-D(FRONT) - 5.62k
  PORT-B(MIC1) - 20k
  PORT-C(LINE_IN1)  -10k
- NP
- HF out
- NP
- NP
- Microphone In
  Line In
  Rear Out
- HDA
- ESD protection
sheet 7
- SDIO
- MISC
- MISC CONNECTOR
- SPI BIOS EXT
- UART 0
- DDI0
- PCIE 1
- USB3
- LPC
- PCIE CLK
- PCIE 2
- USB (ext conn.)
- SATA 0
- HDA
- PCIE 0
- SATA1
- eDP/LVDS
- USB (int. conn.)
- GBE LAN
- SMBus
